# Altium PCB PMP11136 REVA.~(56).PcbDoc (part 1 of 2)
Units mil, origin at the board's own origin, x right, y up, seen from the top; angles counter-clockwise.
Board outline 4320 x 3450 mil, 4 copper layers (Top Layer, Signal Layer 1, Signal Layer 2, Bottom Layer), stack 79.834 mil thick; 234 components, 94 nets, 538 pads, 218 vias.
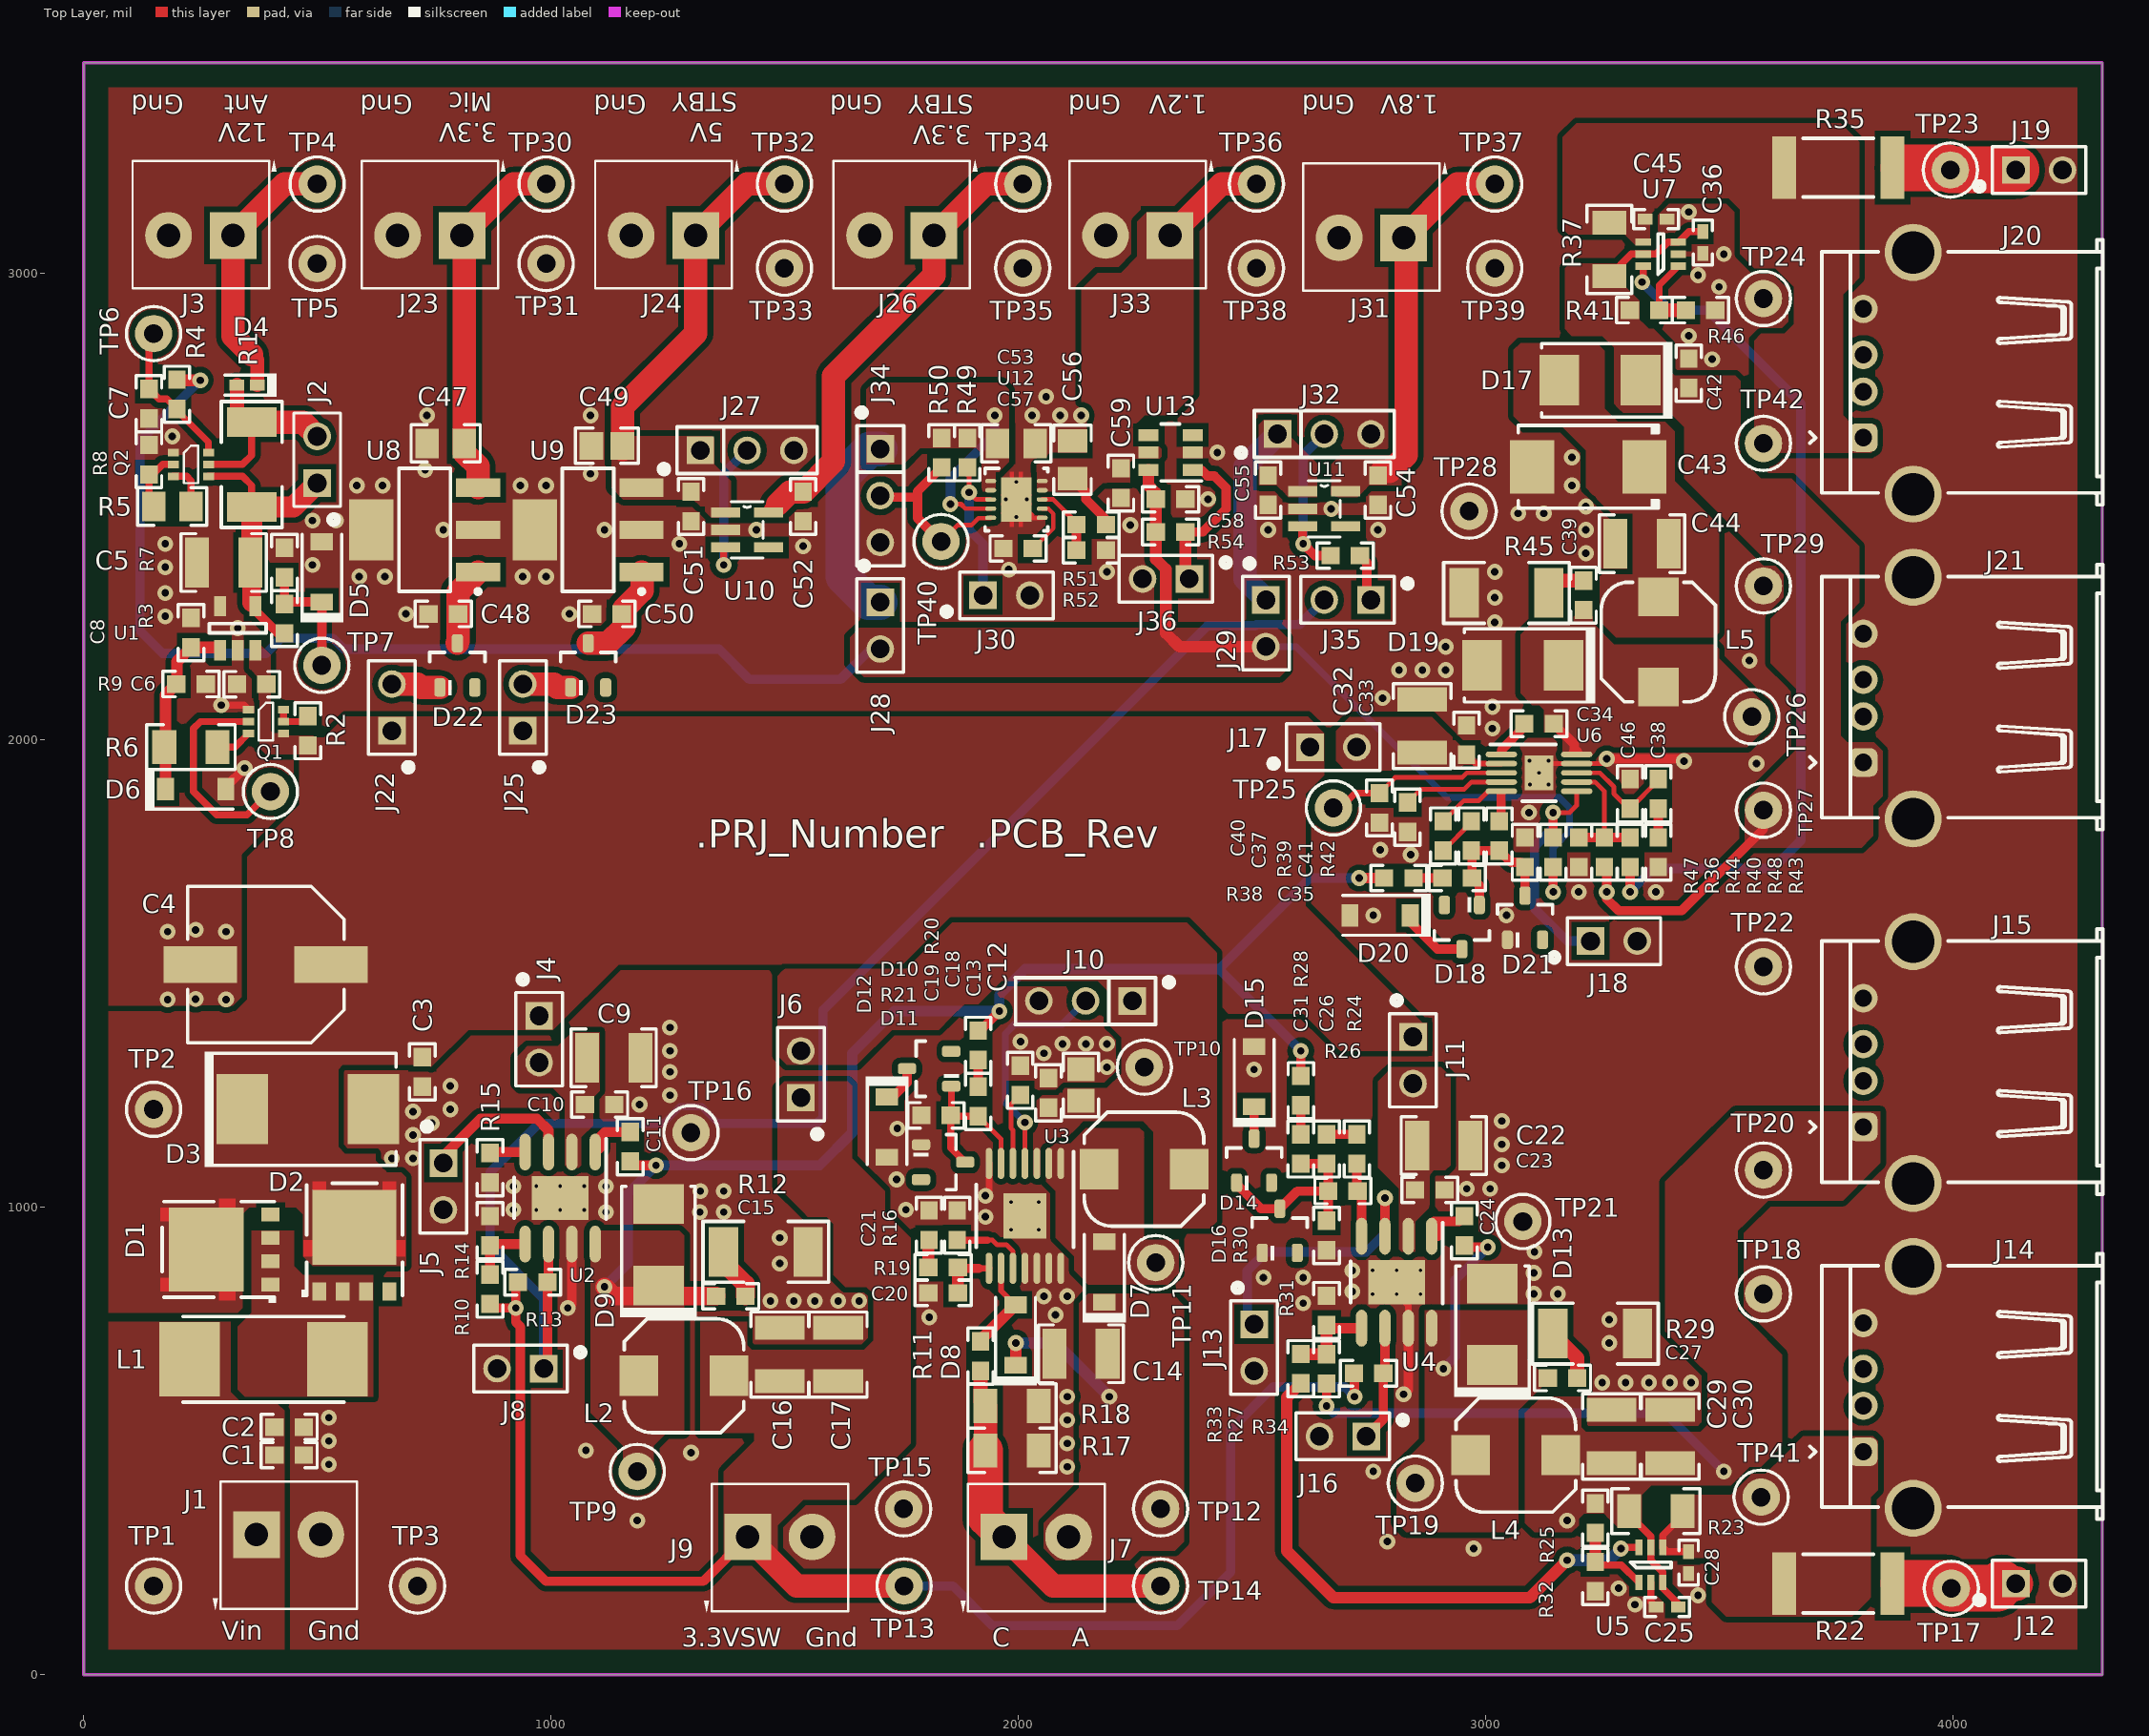
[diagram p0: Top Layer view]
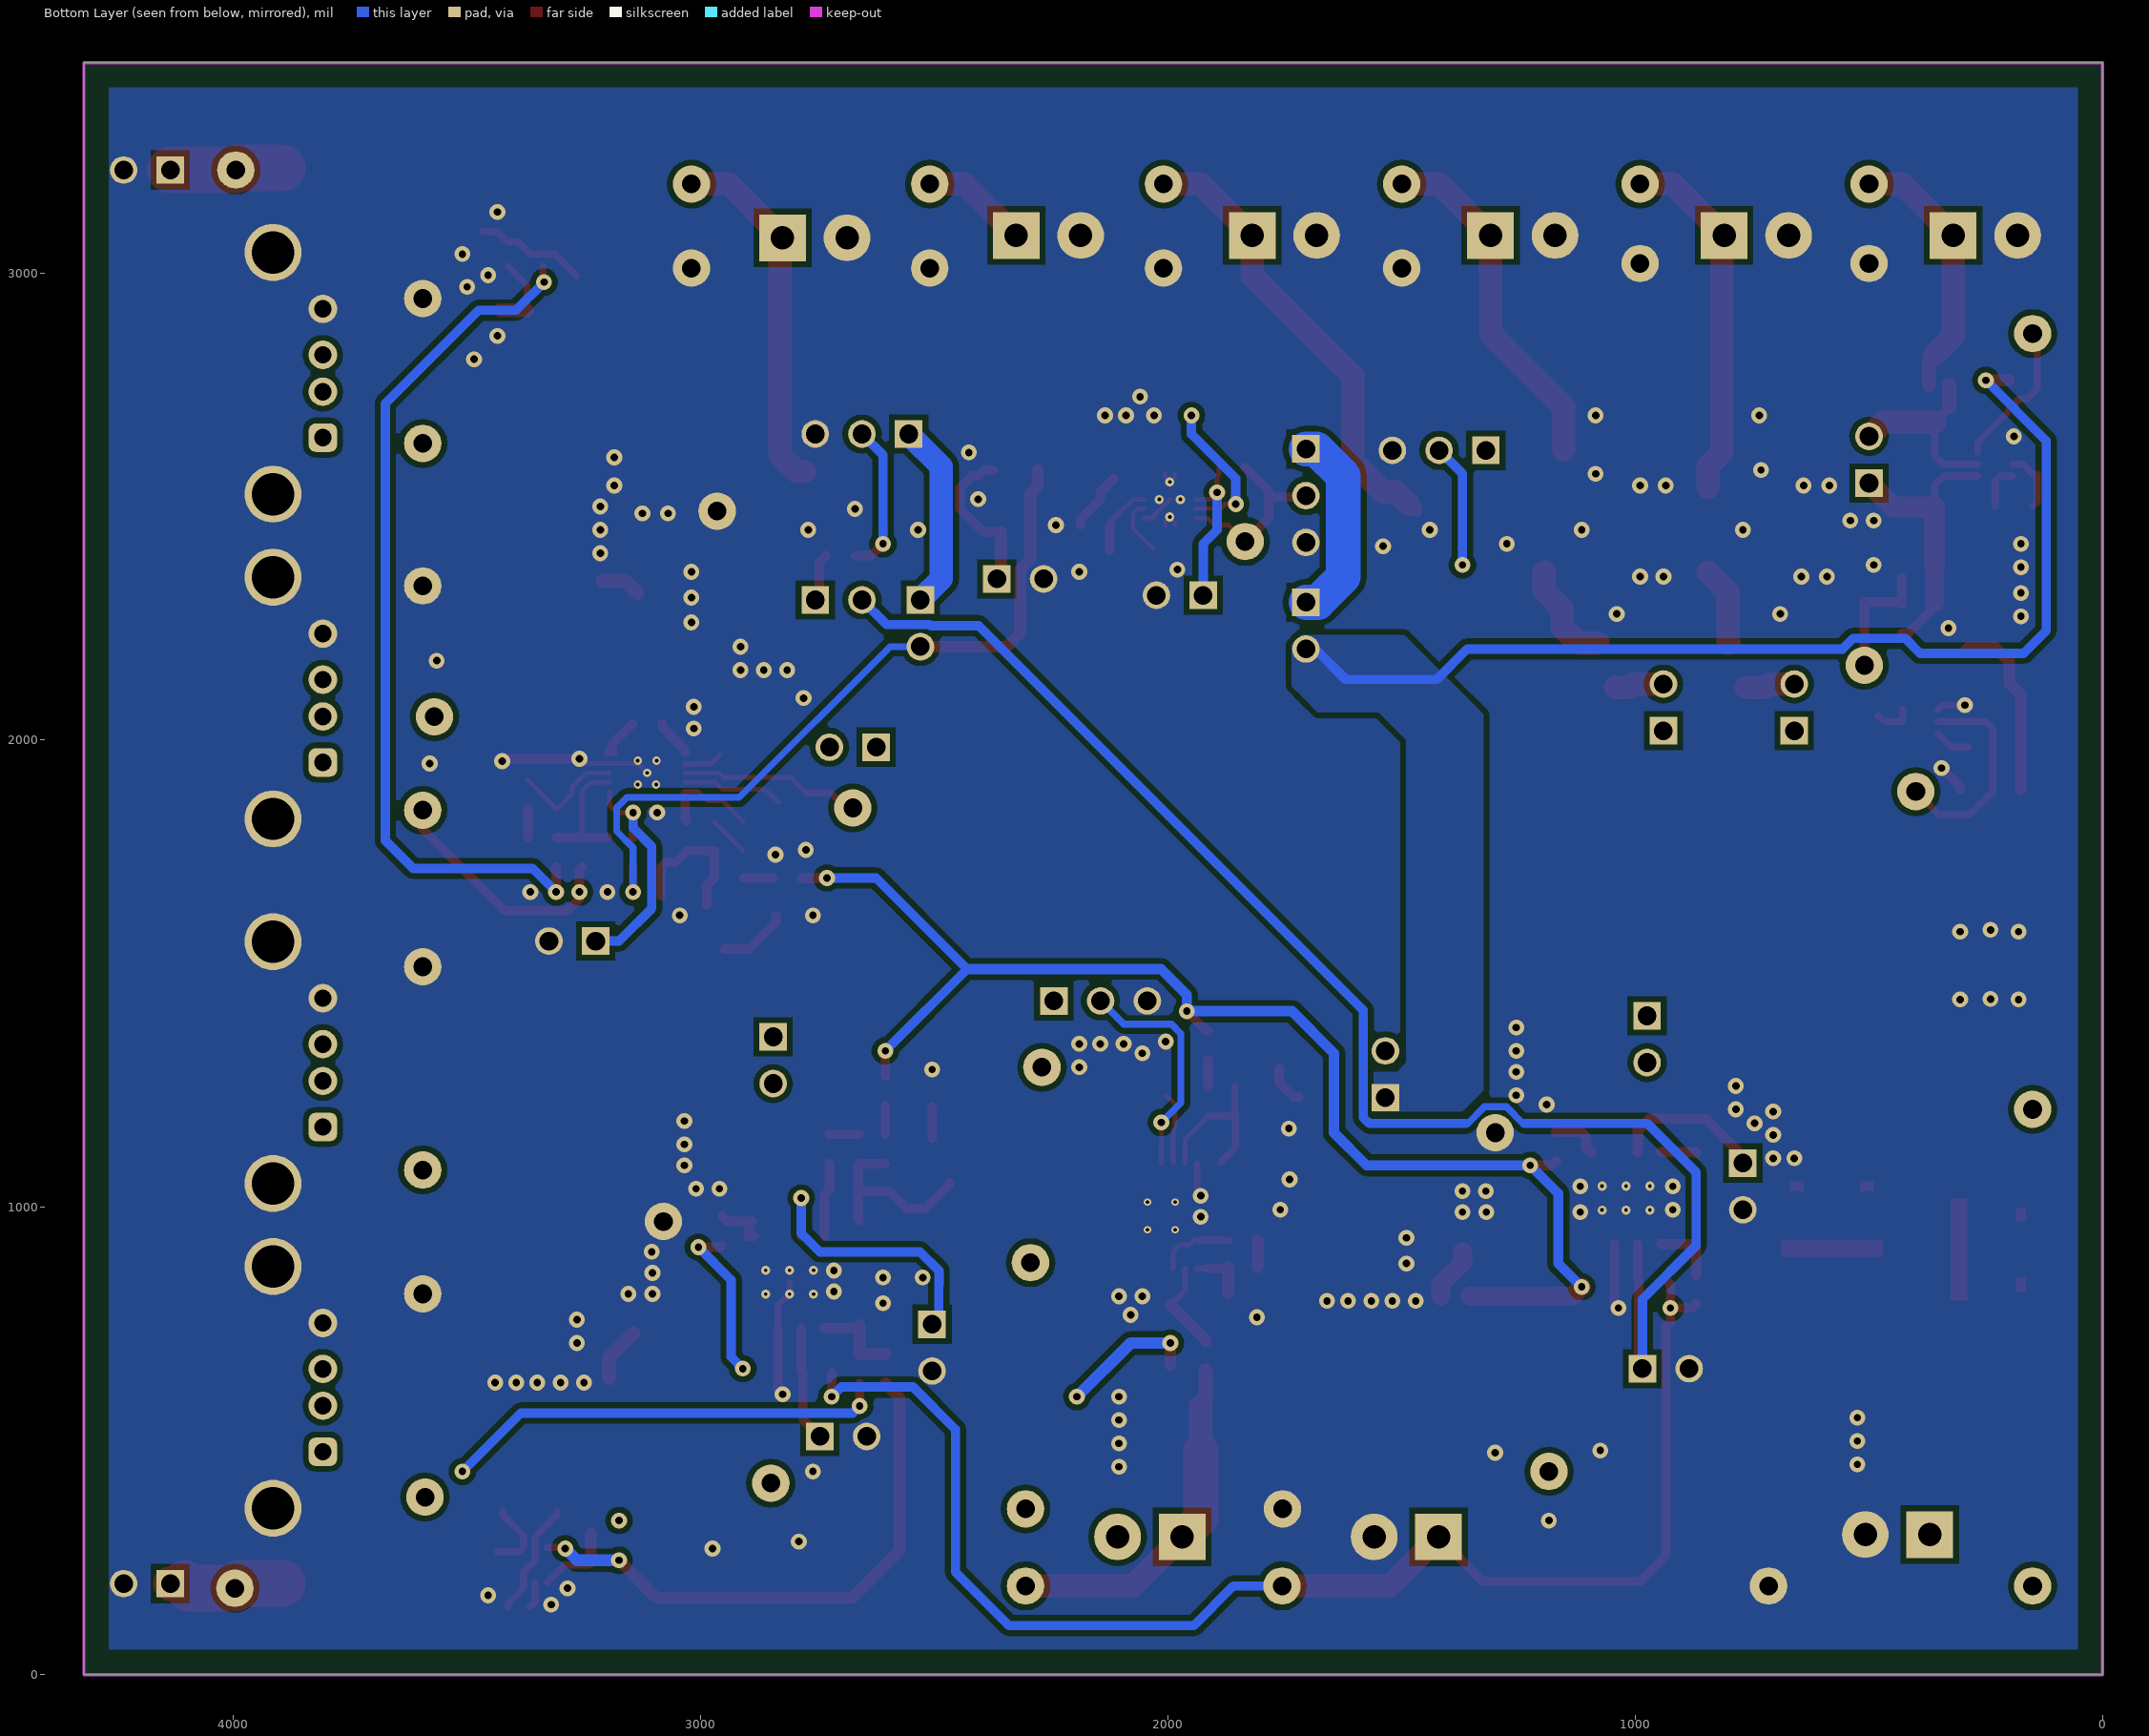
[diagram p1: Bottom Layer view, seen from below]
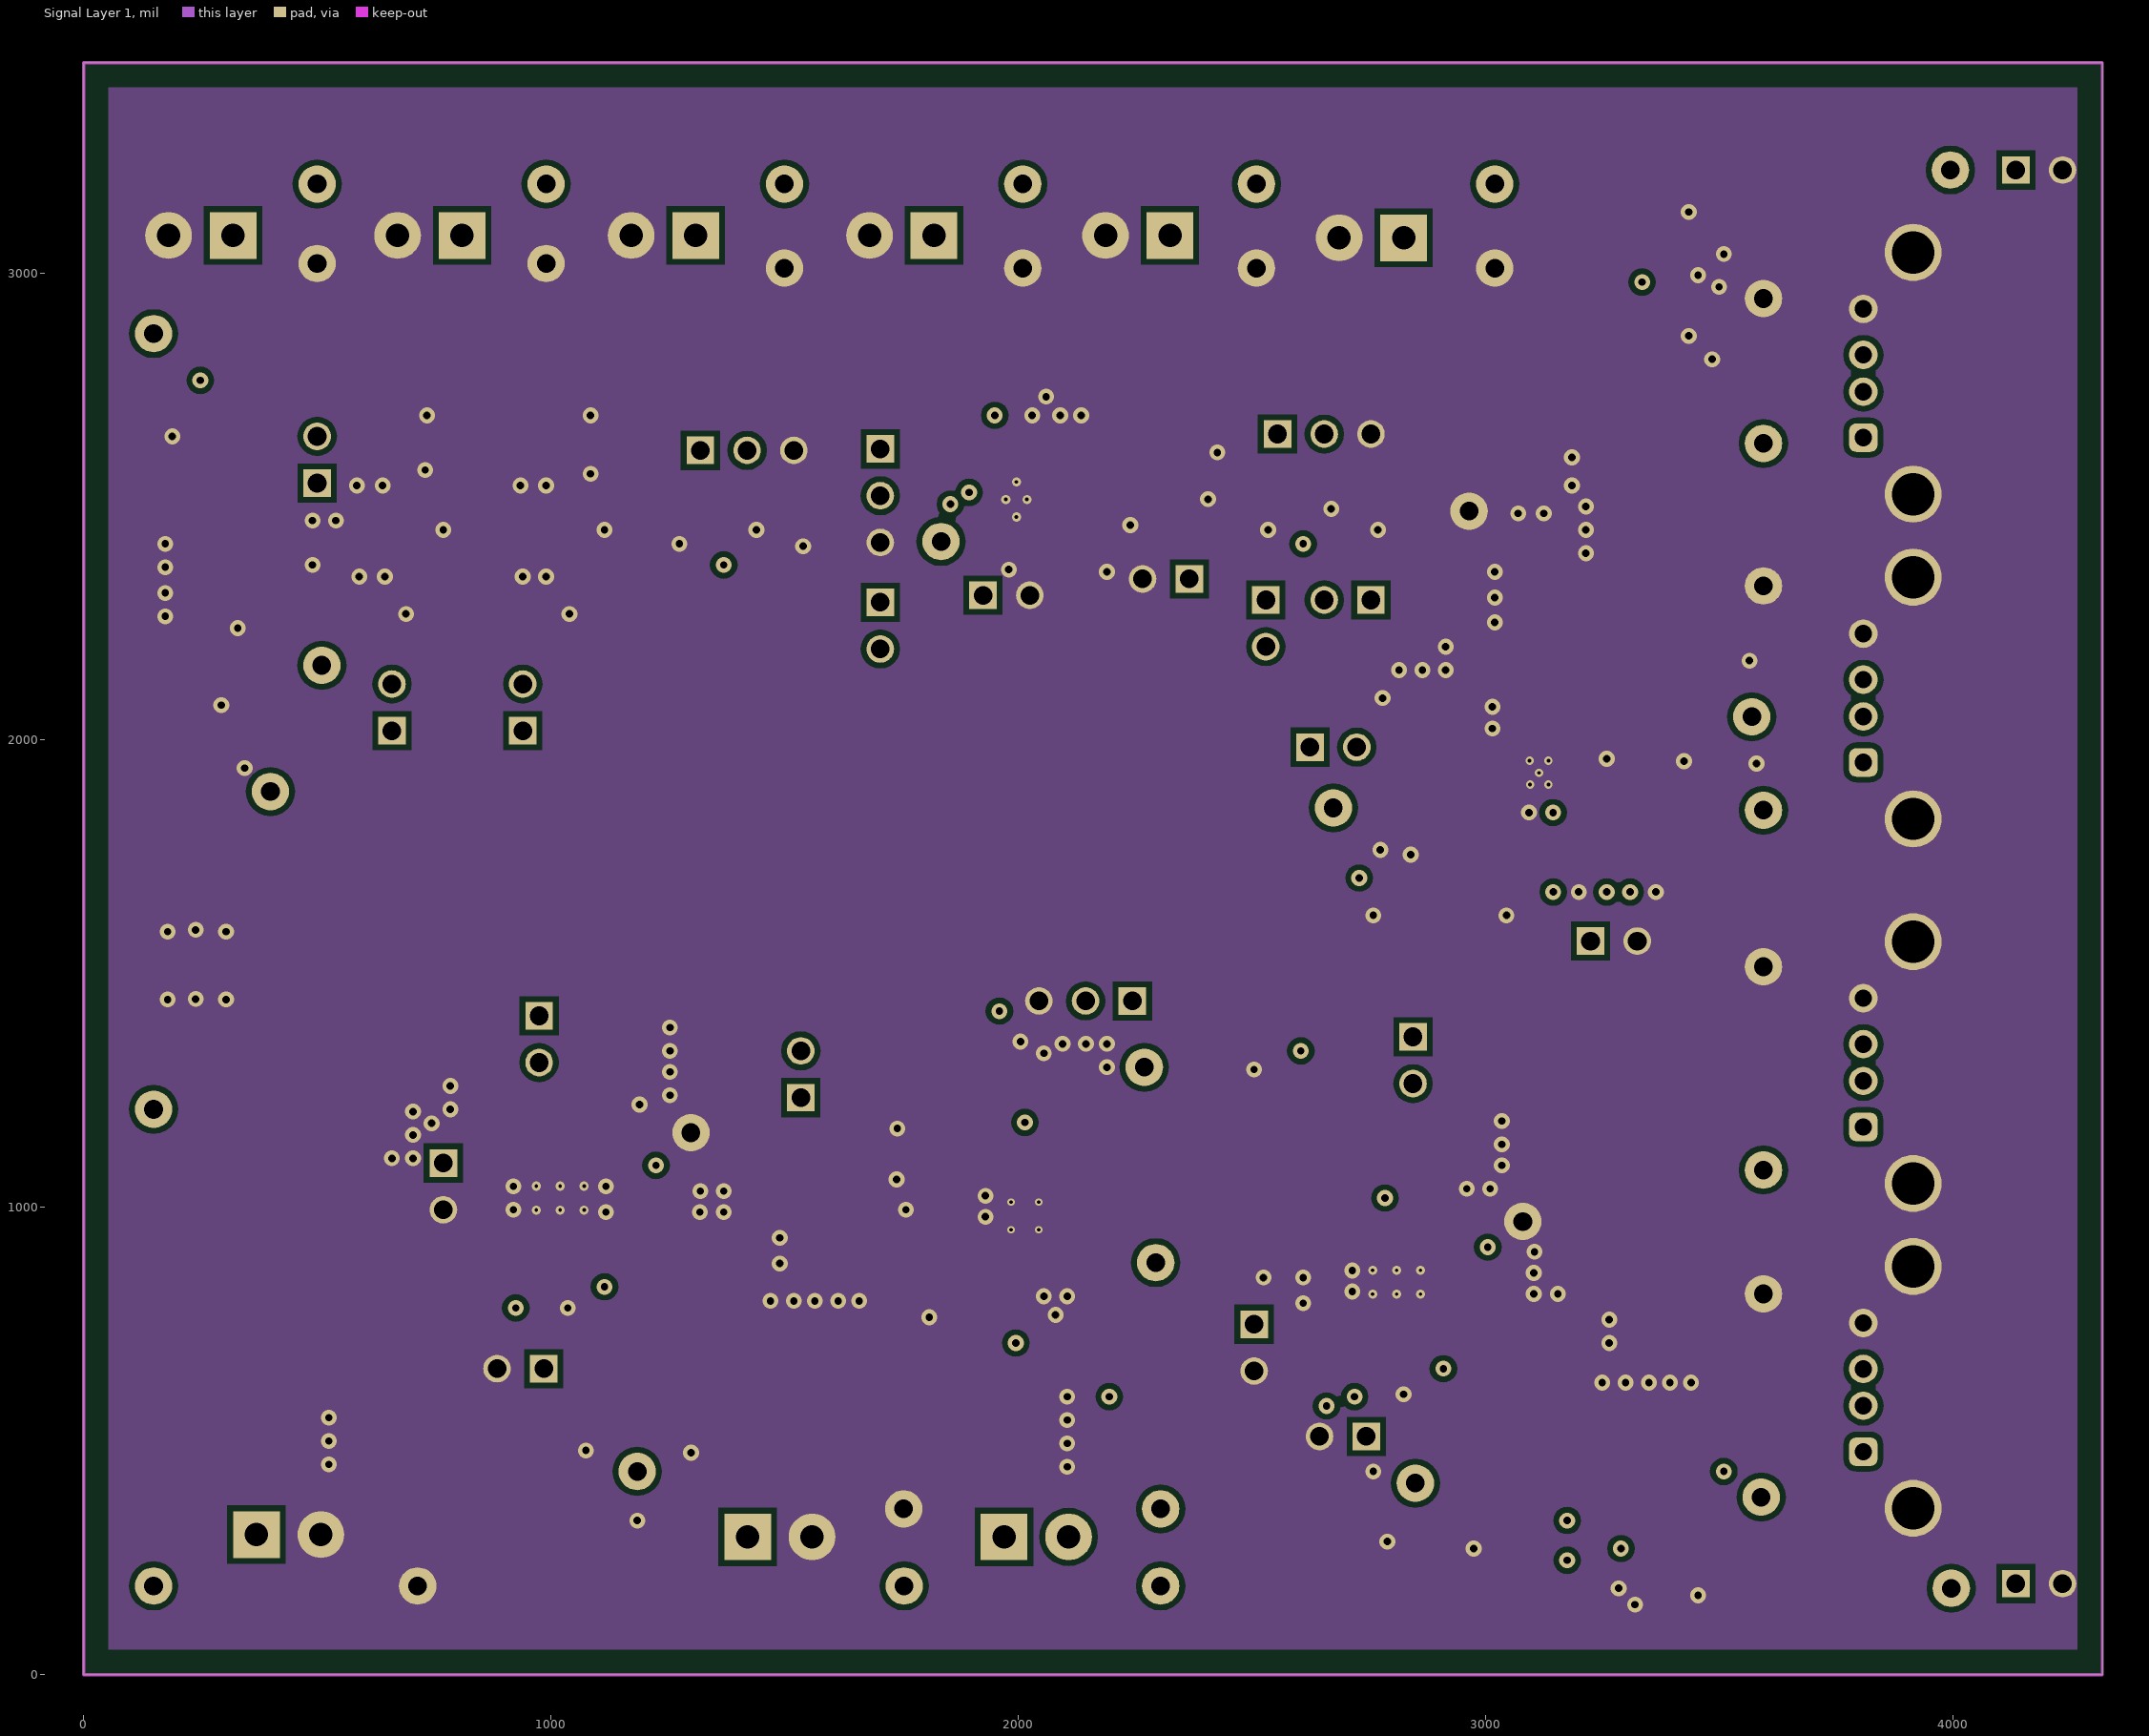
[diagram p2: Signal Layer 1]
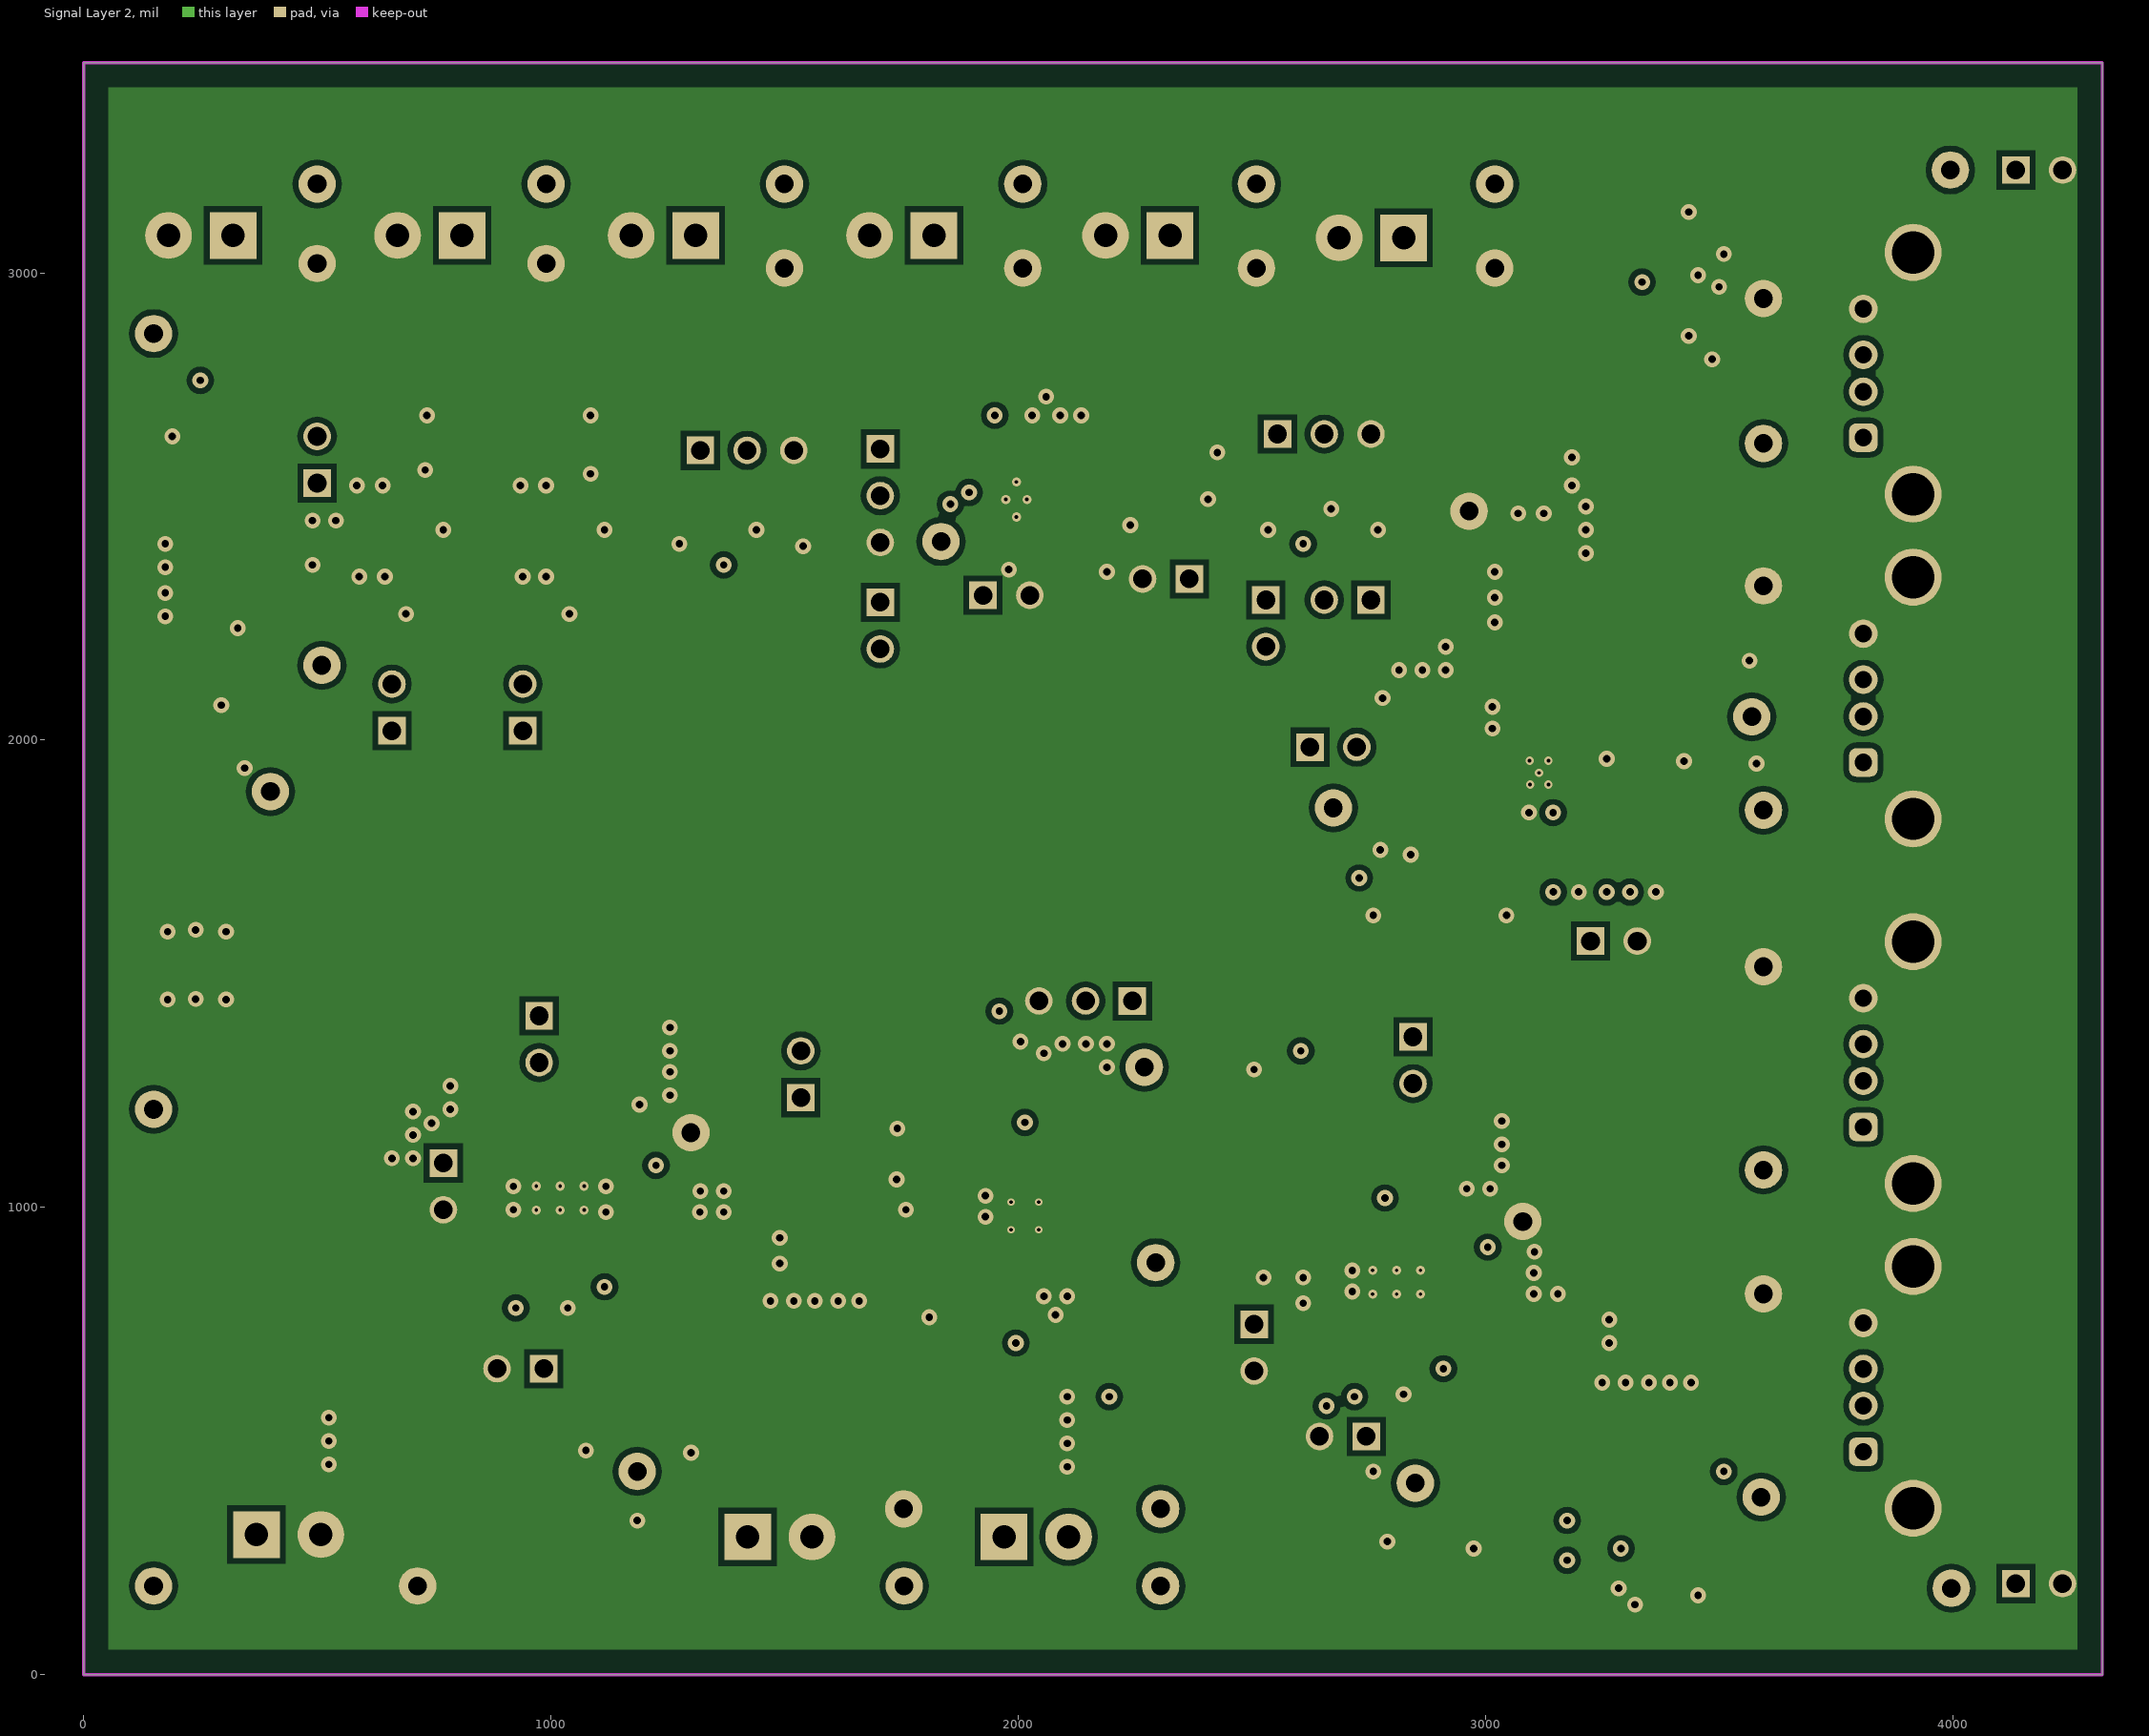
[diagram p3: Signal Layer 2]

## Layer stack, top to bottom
Top Solder: solder mask 0.4, Solder Resist, Dk 3.5
Top Layer: signal copper 1.4
Dielectric1: core 59.2, FR-4, Dk 4.8
Signal Layer 1: signal copper 1.417
Dielectric 3: prepreg 5, Dk 4.2
Signal Layer 2: signal copper 1.417
Dielectric 2: core 10, Dk 4.2
Bottom Layer: signal copper 1.4
Bottom Solder: solder mask 0.4, Solder Resist, Dk 3.5

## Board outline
0,0 4320,0 4320,3450 0,3450

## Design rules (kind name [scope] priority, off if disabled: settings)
AcuteAngle [All] p1: minimum=4.50000000000000E+0001 checktracksonly=FALSE
AssemblyTestPointUsage [All] p1: valid=2
Clearance Clearance_Keepouts [((IsTrack Or IsArc) And Not InPoly) And IsFree and IsKeepOut vs ((IsTrack Or IsArc) And Not InPoly) And IsFree and IsKeepOut] p1: gap=0
Clearance Clearance_BoardEdge_MountingHoles [OnCopper and InComponentClass('Mounting Holes') vs IsKeepOut] p2: gap=40
Clearance Clearance_BoardEdge_Poly [OnCopper and InPoly vs IsKeepOut] p3: gap=50
Clearance Clearance_BoardEdge [OnCopper and Not InComponentClass('Logo') and not InComponentClass('FiducialMark') and not InRegion(1000,500,4000,800) and Not IsKeepout vs IsKeepOut] p4: gap=50
Clearance Clearance_Poly [InPolygon] p5: gap=12
Clearance [All] p6: gap=7.87
ComponentClearance ComponentClearance_MountingHoles_FiducialMarks [InComponentClass('Mounting Holes') vs InComponentClass('FiducialMark')] p1: gap=50 collisioncheckmode=3 verticalgap=10 showdistances=FALSE
ComponentClearance ComponentClearance_Shunt [InComponentClass('Header') vs InComponentClass('Shunt')] p2: gap=0 collisioncheckmode=3 verticalgap=0 showdistances=FALSE
ComponentClearance ComponentClearance_Logo [InComponentClass('Logo')] p3: gap=50 collisioncheckmode=3 verticalgap=10 showdistances=FALSE
ComponentClearance ComponentClearance_ScrewToNut [(HasFootprint('NY PMS 440 0025 PH')) vs (HasFootprint('Keystone_1902C'))] p4: gap=5 collisioncheckmode=3 verticalgap=10 showdistances=FALSE
ComponentClearance ComponentClearance_MountingHoles [InComponentClass('Mounting Holes')] p5: gap=50 collisioncheckmode=3 verticalgap=100000 showdistances=FALSE
ComponentClearance ComponentClearance_SmallPassives [HasFootprint('0201*') or HasFootprint('0402*') or HasFootprint('0508') or HasFootprint('0603*') or HasFootprint('0612') or HasFootprint('0805*') or HasFootprint('0815*') or HasFootprint('0830*') or HasFootprint('1206*') or HasFootprint('1210*') or HasFootprint('1808*') or HasFootprint('1812*') or HasFootprint('1825*') or HasFootprint('2010*') or HasFootprint('2220*') or HasFootprint('2225*') or HasFootprint('2512*') or HasFootprint('2728*') or HasFootprint('3518*') vs HasFootprint('0201*') or HasFootprint('0402*') or HasFootprint('0508') or HasFootprint('0603*') or HasFootprint('0612') or HasFootprint('0805*') or HasFootprint('0815*') or HasFootprint('0830*') or HasFootprint('1206*') or HasFootprint('1210*') or HasFootprint('1808*') or HasFootprint('1812*') or HasFootprint('1825*') or HasFootprint('2010*') or HasFootprint('2220*') or HasFootprint('2225*') or HasFootprint('2512*') or HasFootprint('2728*') or HasFootprint('3518*')] p6: gap=10 collisioncheckmode=3 verticalgap=10 showdistances=FALSE
ComponentClearance ComponentClearance_THtoSMT [IsThruComponent vs IsSMTComponent] p7: gap=25 collisioncheckmode=3 verticalgap=30 showdistances=FALSE
ComponentClearance ComponentClearance_THtoTH [IsThruComponent vs IsThruComponent] p8: gap=25 collisioncheckmode=3 verticalgap=25 showdistances=FALSE
ComponentClearance [All] p9: gap=15 collisioncheckmode=3 verticalgap=10 showdistances=FALSE
DiffPairsRouting [All] p1: maxlimit=100 minlimit=10 mostfreqgap=10 toplayer_minwidth=15 toplayer_maxwidth=15 toplayer_prefwidth=15 midlayer1_minwidth=15 midlayer1_maxwidth=15 midlayer1_prefwidth=15 midlayer2_minwidth=15 midlayer2_maxwidth=15 midlayer2_prefwidth=15 bottomlayer_minwidth=15 bottomlayer_maxwidth=15 bottomlayer_prefwidth=15 maxuncoupledlength=1000
FabricationTestPointUsage TestPointUsage [All] p1: valid=2 allowmultiple=FALSE
FabricationTestpoint Testpoint [All] p1: side=3 testpointundercomponent=TRUE minsize=40 maxsize=100 preferedsize=60 minholesize=0 maxholesize=40 preferedholesize=32 testpointgrid=1 allowsidetop=TRUE allowsidebottom=TRUE usegrid=TRUE gridtolerance=0.01
FanoutControl Fanout_LCC [IsLCC] p1: bgadir=Out bgaviamode=Centered fanoutstyle=Auto fanoutdirection=Alternating viagrid=1 // Fanout_LCC (Default Rule)
FanoutControl Fanout_BGA [IsBGA] p2: bgadir=Out bgaviamode=Centered fanoutstyle=Auto fanoutdirection=Alternating viagrid=1 // Fanout_BGA (Default Rule)
FanoutControl Fanout_Default [All] p4: bgadir=Out bgaviamode=Centered fanoutstyle=Auto fanoutdirection=Alternating viagrid=1 // Fanout_Default (Default Rule)
FanoutControl Fanout_Small [(CompPinCount < 5)] p5: bgadir=Out bgaviamode=Centered fanoutstyle=Auto fanoutdirection=OutThenIn viagrid=1 // Fanout_Small (Default Rule)
HoleSize [All] p1: absolutevalues=TRUE maxlimit=251 minlimit=8 maxpercent=80.000 minpercent=20.000
MinimumAnnularRing MinimumAnnularRing_ThermalPadVias [IsVia and InAnyComponent] p1: minimumring=5.91
MinimumAnnularRing [All] p2: minimumring=9
MinimumSolderMaskSliver MinimumSolderMaskSliver_Logo [InComponentClass('Logo') vs InComponentClass('Logo')] p1: minsoldermaskwidth=0.7
MinimumSolderMaskSliver [All] p2: minsoldermaskwidth=3.94
PlaneClearance [All] p1: clearance=12
PlaneConnect [All] p1: planeconnectstyle=Direct reliefexpansion=10 reliefentries=4 reliefconductorwidth=10 reliefairgap=10
PolygonConnect [All] p1: connectstyle=Direct reliefconductorwidth=10 reliefentries=4 polygonreliefangle="90 Angle" airgapwidth=10
RoutingVias ThermalPadVias [IsVia and InAnyComponent] p1: holewidth=7.87 width=19.68 viastyle="Through Hole" minholewidth=7.87 minwidth=19.68 maxholewidth=12.99 maxwidth=23.62
RoutingVias [All] p2: holewidth=16 width=34 viastyle="Through Hole" minholewidth=7.87 minwidth=26 maxholewidth=40 maxwidth=65
SilkToBoardRegionClearance [Not ((IsComment or IsDesignator) And (Hide <> 'False')) and not InRegion(1000,500,4000,800)] p1:
SilkToSilkClearance SilkToSilkClearance_Pb-FreeLogo [(HasFootprint('Pb-Free_Overlay_Medium') OR HasFootprint('Pb-Free_Overlay_Small')) vs (HasFootprint('Pb-Free_Overlay_Medium') OR HasFootprint('Pb-Free_Overlay_Small'))] p1: silktosilkclearance=0
SilkToSilkClearance [All] p2: silktosilkclearance=0
SilkToSolderMaskClearance "Silk to Solder Mask Opening" [All] p1: minsilkscreentomaskgap=1 clearancetoexposedcopper=FALSE
SolderMaskExpansion [All] p1: expansion=1.97
UnpouredPolygon [All] p1: allowunpoured=FALSE
Width [All] p1: maxlimit=100 minlimit=6 preferedwidth=10 checkconnectedcopper=TRUE
13 further rules are at their usual default settings.

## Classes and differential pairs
component class Header: J2 J4 J5 J6 J8 J10 J11 J12 J13 J16 J17 J18 J19 J22 J25 J27 J28 J29 J30 J32 J34 J35 J36
component class "PMP11136 REVA SHEET1": C1 C2 C3 C4 C5 C6 C7 C8 C9 C10 C11 C12 C13 C14 C15 C16 C17 C18 C19 C20 C21 D1 D2 D3 D4 D5 D6 D7 D8 D9 D10 D11 D12 J1 J2 J3 J4 J5 J6 J7 J8 J9 J10 L1 L2 L3 Q1 Q2 R1 R2 R3 R4 R5 R6 R7 R8 R9 R10 R11 R12 R13 R14 R15 R16 R17 R18 R19 R20 R21 TP1 TP2 TP3 TP4 TP5 TP6 TP7 TP8 TP9 TP10 TP11 TP12 TP13 TP14 TP15 TP16 U1 U2 U3
component class "PMP11136 REVA SHEET2": C22 C23 C24 C25 C26 C27 C28 C29 C30 C31 C32 C33 C34 C35 C36 C37 C38 C39 C40 C41 C42 C43 C44 C45 C46 D13 D14 D15 D16 D17 D18 D19 D20 D21 J11 J12 J13 J14 J15 J16 J17 J18 J19 J20 J21 L4 L5 R22 R23 R24 R25 R26 R27 R28 R29 R30 R31 R32 R33 R34 R35 R36 R37 R38 R39 R40 R41 R42 R43 R44 R45 R46 R47 R48 TP17 TP18 TP19 TP20 TP21 TP22 TP23 TP24 TP25 TP26 TP27 TP28 TP29 TP41 TP42 U4 U5 U6 U7
component class "PMP11136 REVA SHEET3": C47 C48 C49 C50 C51 C52 C53 C54 C55 C56 C57 C58 C59 D22 D23 J22 J23 J24 J25 J26 J27 J28 J29 J30 J31 J32 J33 J34 J35 J36 R49 R50 R51 R52 R53 R54 TP30 TP31 TP32 TP33 TP34 TP35 TP36 TP37 TP38 TP39 TP40 U8 U9 U10 U11 U12 U13

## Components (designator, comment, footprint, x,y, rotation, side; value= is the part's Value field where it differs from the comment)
C1 "C1608C0G2A102J" 0603 440,470 r0 top
C2 "C1608X7R2A103K" 0603 440,530 r0 top
C3 "C1608X7R1H224K080AB" 0603 725,1290 r270 top
C4 "EEE-FK1H101P" SM_RADIAL_F 390,1520 r180 top
C5 "C3225X7R1H475M250AB" 1210 300,2380 r0 top
C6 "C1608X7R1E105K" 0603 360,2119.68 r180 top
C7 "C1608X7R1H104K" 0603 140,2720 r270 top
C8 "C1608X7R1H103K" 0603 230,2230 r90 top
C9 "C3225X7R1H475M250AB" 1210 1134.43,1320 r180 top
C10 "C1608X7R1H104K" 0603 1104.43,1220 r0 top
C11 "C1608X7R1H104K" 0603 1170,1130 r270 top
C12 "GRM21BR71A106KE51L" 0805 2134.49,1261.91 r90 top
C13 "C1608X7R1E105K" 0603 2065,1245 r90 top
C14 "C3225X7R1C226M250AC" 1210 2134.49,686.91 r180 top
C15 "" 0603 1385,810 r0 top
C16 "C3225X7R1C226M250AC" 1210 1490,685 r90 top
C17 "" 1210 1615,685 r90 top
C18 "C1608X7R1H473K" 0603 2004.49,1271.91 r90 top
C19 "C1608C0G1H151J" 0603 1914.49,1226.91 r90 top
C20 "" 0603 1839.49,816.91 r180 top
C21 "C1608C0G1E682J" 0603 1809.49,961.91 r90 top
C22 "C3225X7R1H475M250AB" 1210 2911,1132.52 r180 top
C23 "C1608X7R1H104K" 0603 2881,1037.52 r0 top
C24 "C1608X7R1H104K" 0603 2955,950 r270 top
C25 "C1005X7R1H104K050BB" 0402 3389.01,145 r180 top
C26 "C1608C0G1H100D" 0603 2660,1125 r270 top
C27 "" 0603 3165,635 r0 top
C28 "C1005X7R1H104K050BB" 0402 3435,240 r270 top
C29 "C3225X7R1C226M250AC" 1210 3270,510 r90 top
C30 "" 1210 3395,510 r90 top
C31 "C1608C0G1H151J" 0603 2605,1125 r90 top
C32 "C3225X7R1H475M250AB" 1210 2864.68,2030 r270 top
C33 "C1608X7R1H104K" 0603 2959.68,2000 r90 top
C34 "C1608X7R1H104K" 0603 3114.68,2035 r0 top
C35 "C1608C0G1H151J" 0603 2939.68,1705 r180 top
C36 "C1005X7R1H104K050BB" 0402 3465.31,3065 r270 top
C37 "C1608X7R1H223K" 0603 2833.23,1835 r270 top
C38 "C1608C0G1H152J" 0603 3369.68,1885 r270 top
C39 "" 0603 3210,2310 r90 top
C40 "" 0603 2773.23,1855 r270 top
C41 "C1608C0G1H100D" 0603 2969.68,1795 r270 top
C42 "C1608X7R1H104K" 0603 3435,2785 r90 top
C43 "" 7343-40 3220,2585 r180 top
C44 "C3225X7R1C226M250AC" 1210 3335,2420 r180 top
C45 "C1005X7R1H104K050BB" 0402 3365.31,3115 r0 top
C46 "C1608C0G1H100D" 0603 3309.68,1885 r90 top
C47 "GRM21BR71A106KE51L" 0805_HV 775,2635 r180 top
C48 "C1608X7R1H104K" 0603 770,2270 r180 top
C49 "GRM21BR71A106KE51L" 0805 1120,2630 r180 top
C50 "C1608X7R1H104K" 0603 1120,2270 r180 top
C51 "C1608X7R1E105K" 0603 1300,2500 r270 top
C52 "C1608X7R1E105K" 0603 1540,2500 r270 top
C53 "GRM21BR71A106KE51L" 0805_HV 1996.3,2635 r0 top
C54 "C1608X7R1E105K" 0603 2770,2535 r270 top
C55 "C1608X7R1E105K" 0603 2535,2535 r270 top
C56 "GRM21BR71A106KE51L" 0805_HV 2116.3,2600 r90 top
C57 "" 0603 2000,2410 r180 top
C58 "C1608X7R1H104K" 0603 2326.3,2515.47 r0 top
C59 "C1608C0G2A102J" 0603 2220,2550 r270 top
D1 "MBR1045MFST1G" SO-8FL 290,910 r180 top
D2 "MBR1045MFST1G" SO-8FL 580,930 r90 top
D3 "1.5SMC33AT3G" SMC 480,1210 r0 top
D4 "1PS79SB30" SOD-523 350,2760 r180 top
D5 "MMSZ4684T1G" SOD-123 510,2360 r90 top
D6 "MMSZ4705T1G" SOD-123 240,1895 r0 top
D7 "RB070M-30" SOD-123 2184.49,861.91 r90 top
D8 "MMSZ4699T1G" SOD-123 1994.49,726.91 r90 top
D9 "MBRS360BT3G" SMB 1230.31,920 r90 top
D10 "BAS16-7-F" SOT-23 1809.49,1296.91 r180 top
D11 "BAS16-7-F" SOT-23 1839.49,1096.91 r0 top
D12 "MMSZ5221B-7-F" SOD-123 1719.49,1171.91 r270 top
D13 "MBRS360BT3G" SMB 3015,750 r90 top
D14 "BAS16-7-F" SOT-23 2505,1100 r90 top
D15 "MMSZ5221B-7-F" SOD-123 2505,1280 r90 top
D16 "BAS16-7-F" SOT-23 2560,950 r90 top
D17 "MBRS260T3G" SMB 3245,2770 r180 top
D18 "BAS16-7-F" SOT-23 2949.68,1600 r270 top
D19 "MBRS260T3G" SMB 3080,2160 r180 top
D20 "MMSZ5221B-7-F" SOD-123 2774.68,1625 r180 top
D21 "BAS16-7-F" SOT-23 3084.68,1620 r90 top
D22 "BAS16-7-F" SOT-23 800,2160 r90 top
D23 "BAS16-7-F" SOT-23 1080,2160 r90 top
J1 "ED555/2DS" TERM_BLK_ED555-2DS 370,300 r0 top
J2 "PEC02SAAN" CONN_PEC02SAAN 500,2600 r90 top
J3 "ED555/2DS" TERM_BLK_ED555-2DS 320,3080 r180 top
J4 "PEC02SAAN" CONN_PEC02SAAN 975,1360 r270 top
J5 "PEC02SAAN" CONN_PEC02SAAN 770,1045 r270 top
J6 "PEC02SAAN" CONN_PEC02SAAN 1535,1285 r90 top
J7 "ED555/2DS" TERM_BLK_ED555-2DS 1970,295 r0 top
J8 "PEC02SAAN" CONN_PEC02SAAN 935,655 r180 top
J9 "ED555/2DS" TERM_BLK_ED555-2DS 1421.1,295 r0 top
J10 "PEC03SAAN" CONN_PEC03SAAN 2144.49,1441.91 r180 top
J11 "PEC02SAAN" CONN_PEC02SAAN 2845,1315 r270 top
J12 "PEC02SAAN" CONN_PEC02SAAN 4185,195 r0 top
J13 "PEC02SAAN" CONN_PEC02SAAN 2505,700 r270 top
J14 "676430910" MOLEX_0676430910 3915,615 r90 top
J15 "676430910" MOLEX_0676430910 3915,1310 r90 top
J16 "PEC02SAAN" CONN_PEC02SAAN 2695,510 r180 top
J17 "PEC02SAAN" CONN_PEC02SAAN 2674.68,1985 r0 top
J18 "PEC02SAAN" CONN_PEC02SAAN 3275,1570 r0 top
J19 "PEC02SAAN" CONN_PEC02SAAN 4185,3220 r0 top
J20 "676430910" MOLEX_0676430910 3915,2785 r90 top
J21 "676430910" MOLEX_0676430910 3915,2090 r90 top
J22 "PEC02SAAN" CONN_PEC02SAAN 660,2070 r90 top
J23 "ED555/2DS" TERM_BLK_ED555-2DS 810,3080 r180 top
J24 "ED555/2DS" TERM_BLK_ED555-2DS 1310,3080 r180 top
J25 "PEC02SAAN" CONN_PEC02SAAN 940,2070 r90 top
J26 "ED555/2DS" TERM_BLK_ED555-2DS 1820,3080 r180 top
J27 "PEC03SAAN" CONN_PEC03SAAN 1420,2620 r0 top
J28 "PEC02SAAN" CONN_PEC02SAAN 1705,2245 r270 top
J29 "PEC02SAAN" CONN_PEC02SAAN 2530,2250 r270 top
J30 "PEC02SAAN" CONN_PEC02SAAN 1975,2310 r0 top
J31 "ED555/2DS" TERM_BLK_ED555-2DS 2825,3075 r180 top
J32 "PEC03SAAN" CONN_PEC03SAAN 2655,2655 r0 top
J33 "ED555/2DS" TERM_BLK_ED555-2DS 2325,3080 r180 top
J34 "PEC03SAAN" CONN_PEC03SAAN 1705,2523.02 r270 top
J35 "PEC02SAAN" CONN_PEC02SAAN 2705,2300 r180 top
J36 "PEC02SAAN" CONN_PEC02SAAN 2316.3,2345 r180 top
L1 "28F0181-1SR-10" 28F0181 385,675 r0 top
L2 "CLF6045NIT-2R2N-D" CLF6045NI-D 1285,640 r0 top
L3 "CLF6045NIT-4R7N-D" CLF6045NI-D 2269.49,1081.91 r180 top
L4 "CLF6045NIT-2R2N-D" CLF6045NI-D 3065,470 r0 top
L5 "CLF6045NIT-4R7N-D" CLF6045NI-D 3370,2210 r90 top
Q1 "BCR22PN" SOT-363 390.35,2039.77 r0 top
Q2 "BC847PN" SOT-363 230,2590 r0 top
R1 "CRCW20107R50JNEF" 2010 360,2589.69 r90 top
R2 "CRCW060320K0FKEA" 0603 480,2020 r270 top
R3 "CRCW060310K0FKEA" 0603 430,2260 r270 top
R4 "CRCW060310K0FKEA" 0603 200,2740 r90 top
R5 "CRCW080510K0FKEA" 0805_HV 190,2500 r0 top
R6 "CRCW12062K00FKEA" 1206 230,1985 r180 top
R7 "CRCW06032K87FKEA" 0603 430,2380 r90 top
R8 "CRCW06033K01FKEA" 0603 140,2600 r270 top
R9 "CRCW0603100KFKEA" 0603 230,2120 r0 top
R10 "CRCW060334K0FKEA" 0603 870,825 r270 top
R11 "CRCW0603110RFKEA" 0603 1919.49,681.91 r90 top
R12 "" 2010 1460,905 r180 top
R13 "CRCW060310K0FKEA" 0603 961.3,840 r0 top
R14 "CRCW060310K0FKEA" 0603 870,950 r270 top
R15 "" 0603 870,1085 r90 top
R16 "CRCW060353K6FKEA" 0603 1869.49,961.91 r270 top
R17 "CRCW120615R0FKEA" 1206 1987.09,480 r180 top
R18 "CRCW120615R0FKEA" 1206 1987.09,575 r180 top
R19 "CRCW060310K0FKEA" 0603 1839.49,871.91 r0 top
R20 "CRCW06030000Z0EA" 0603 1914.49,1346.91 r270 top
R21 "CRCW0603200RFKEA" 0603 1824.49,1196.91 r0 top
R22 "CSRN2512FKR200" 2512 3755,195 r0 top
R23 "CSR1206FK10L0" 1206 3365,350 r0 top
R24 "CRCW06034K02FKEA" 0603 2725,1125 r90 top
R25 "CRCW06034K99FKEA" 0603 3235,335 r270 top
R26 "" 0603 2695,1035 r0 top
R27 "CRCW060363K4FKEA" 0603 2660,654.45 r270 top
R28 "CRCW06030000Z0EA" 0603 2605,1250 r270 top
R29 "" 2010 3235,730 r180 top
R30 "CRCW0603200RFKEA" 0603 2660,940 r90 top
R31 "CRCW060310K0FKEA" 0603 2660,779.45 r270 top
R32 "CRCW06034K99FKEA" 0603 3235,210 r270 top
R33 "CRCW0603124KFKEA" 0603 2605,655 r90 top
R34 "CRCW060310K0FKEA" 0603 2750,645 r0 top
R35 "CSRN2512FKR200" 2512 3755,3225 r0 top
R36 "CRCW060310K0FKEA" 0603 3144.68,1760 r90 top
R37 "CSR1206FK10L0" 1206 3265.31,3050 r90 top
R38 "CRCW06030000Z0EA" 0603 2814.68,1705 r0 top
R39 "CRCW06034K02FKEA" 0603 2909.68,1795 r270 top
R40 "CRCW060363K4FKEA" 0603 3254.68,1760 r270 top
R41 "CRCW06034K99FKEA" 0603 3340.33,2920 r0 top
R42 "CRCW060354K9FKEA" 0603 3029.68,1795 r90 top
R43 "CRCW0603100KFKEA" 0603 3369.68,1760 r90 top
R44 "CRCW060310K0FKEA" 0603 3199.68,1760 r90 top
R45 "" 2010 3045,2315 r0 top
R46 "CRCW06034K99FKEA" 0603 3460.33,2920 r0 top
R47 "CRCW0603200RFKEA" 0603 3084.68,1760 r270 top
R48 "CRCW0603124KFKEA" 0603 3309.68,1760 r90 top
R49 "CRCW060310K0FKEA" 0603 1891.3,2615 r90 top
R50 "CRCW060310K0FKEA" 0603 1836.3,2615 r90 top
R51 "CRCW06032K49FKEA" 0603 2156.3,2461.3 r0 top
R52 "CRCW06034K99FKEA" 0603 2156.3,2406.3 r180 top
R53 "CRCW060310K0FKEA" 0603 2700,2395 r180 top
R54 "CRCW060349K9FKEA" 0603 2326.3,2445.47 r180 top
TP1 "5000" Keystone5000 150,190 r0 top
TP2 "5000" Keystone5000 150,1210 r0 top
TP3 "5001" Keystone5001 715,190 r0 top
TP4 "5000" Keystone5000 500,3190 r0 top
TP5 "5001" Keystone5001 500,3020 r0 top
TP6 "5000" Keystone5000 150,2870 r0 top
TP7 "5000" Keystone5000 510,2160 r0 top
TP8 "5000" Keystone5000 400,1890 r0 top
TP9 "5000" Keystone5000 1185,435 r270 top
TP10 "5000" Keystone5000 2270,1300 r0 top
TP11 "5000" Keystone5000 2294.49,881.91 r270 top
TP12 "5000" Keystone5000 2305,355 r0 top
TP13 "5000" Keystone5000 1756.1,190 r0 top
TP14 "5001" Keystone5001 2305,190 r0 top
TP15 "5001" Keystone5001 1755,355 r0 top
TP16 "5001" Keystone5001 1300,1160 r0 top
TP17 "5000" Keystone5000 3996.97,185 r0 top
TP18 "5001" Keystone5001 3595,815 r0 top
TP19 "5000" Keystone5000 2850,410 r270 top
TP20 "5000" Keystone5000 3595,1080 r0 top
TP21 "5001" Keystone5001 3080,970 r0 top
TP22 "5001" Keystone5001 3595,1515 r0 top
TP23 "5000" Keystone5000 3995,3220 r0 top
TP24 "5001" Keystone5001 3595,2945 r0 top
TP25 "5000" Keystone5000 2674.68,1855 r0 top
TP26 "5000" Keystone5000 3570,2050 r0 top
TP27 "5000" Keystone5000 3595,1850 r0 top
TP28 "5001" Keystone5001 2965,2490 r0 top
TP29 "5001" Keystone5001 3595,2330 r0 top
TP30 "5000" Keystone5000 990,3190 r0 top
TP31 "5001" Keystone5001 990,3020 r0 top
TP32 "5000" Keystone5000 1500,3190 r0 top
TP33 "5001" Keystone5001 1500,3010 r0 top
TP34 "5000" Keystone5000 2010,3190 r0 top
TP35 "5001" Keystone5001 2010,3010 r0 top
TP36 "5000" Keystone5000 2510,3190 r0 top
TP37 "5000" Keystone5000 3020,3190 r0 top
TP38 "5001" Keystone5001 2510,3010 r0 top
TP39 "5001" Keystone5001 3020,3010 r0 top
TP40 "5000" Keystone5000 1835,2425 r180 top
TP41 "5000" Keystone5000 3590,380 r0 top
TP42 "5000" Keystone5000 3595,2635 r0 top
U1 "TPS7B4250QDBV" DBV0005A_N 330,2239.68 r90 top
U2 "LMR14030PQDDAQ1" DDA0008E_N 1020,1020 r270 top
U3 "TPS61175PWP" PWP0014E_N 2014.49,981.91 r270 top
U4 "LMR14030PQDDAQ1" DDA0008E_N 2810,840 r270 top
U5 "INA213AQDCKRQ1" DCK0006A_N 3354.01,235 r90 top
U6 "TPS57140QDGQRQ1" DGQ0010D_NV_N 3114.68,1930 r0 top
U7 "INA213AQDCKRQ1" DCK0006A_N 3375.31,3040 r180 top
U8 "TPS7B6933QDCYRQ1" DCY0004A_N 730,2450 r180 top
U9 "TPS7B6950QDCYRQ1" DCY0004A_N 1080,2450 r180 top
U10 "TLV70033QDDCRQ1" DDC0005A_N 1420,2450 r0 top
U11 "TLV70018QDDCRQ1" DDC0005A_N 2655,2495 r0 top
U12 "TPS74701QDRCRQ1" DRC0010A 1996.3,2515 r0 top
U13 "TPS3808G12QDBVRQ1" DBV0006A_N 2326.3,2615.47 r180 top

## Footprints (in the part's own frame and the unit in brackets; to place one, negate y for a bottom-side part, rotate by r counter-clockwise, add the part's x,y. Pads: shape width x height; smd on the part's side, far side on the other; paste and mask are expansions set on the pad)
28F0181 [mm] "SMD, 2-Leads, Body 8.74x4.65mm"
  rect 3.3x4.06 smd: 1(-4.015,0) 2(4.015,0)
  silkscreen extent -4.37,-2.32 4.37,2.32, body extent -4.76,-2.32 4.77,2.32, height 3.05
0402 [mm] "0402 from SM-752 data"
  rect 0.8x0.6 smd: 1(-0.6,0) 2(0.6,0)
  silkscreen extent -1.22,-0.52 1.22,0.52, body extent -0.55,-0.3 0.55,0.3, height 0.6
0603 [mm] "0603 from SM-752 data"
  rect 1x0.95 smd: 1(-0.8,0) 2(0.8,0)
  silkscreen extent -1.52,-0.69 1.52,0.69, body extent -0.87,-0.47 0.87,0.47, height 0.85
0805 [mm] "0805 from SM-752 data"
  rect 1.3x1.5 smd: 1(-0.85,0) 2(0.85,0)
  silkscreen extent -1.72,-0.97 1.72,0.97, body extent -1.1,-0.72 1.1,0.72, height 1.1
0805_HV [mil] "0805 with 30mil clearance between pads"
  rect 50x63 smd: 1(-40,0) 2(40,0)
  silkscreen extent -74,-40 74,40, body extent -43,-29 43,29, height 43
1206 [mm] "1206 from SM-752 data"
  rect 1.3x1.85 smd: 1(-1.45,0) 2(1.45,0)
  silkscreen extent -2.4,-1.21 2.4,1.21, body extent -1.7,-0.9 1.7,0.9, height 1.35
1210 [mm] "1210 from SM-752 data"
  rect 1.3x2.7 smd: 1(-1.45,0) 2(1.45,0)
  silkscreen extent -2.32,-1.57 2.32,1.57, body extent -1.7,-1.35 1.7,1.35, height 1.35
2010 [mm] "Chip Capacitor, Body 5.08x2.54mm, IPC Medium Density"
  rect 1.6x2.7 smd: 1(-2.3,0) 2(2.3,0)
  silkscreen extent -3.42,-1.65 3.42,1.65, body extent -2.73,-1.45 2.73,1.45, height 1.66
2512 [mm] "Chip Resistor, Body 6.3x3.2mm, IPC Medium Density"
  rect 1.3x3.4 smd: 1(-2.95,0) 2(2.95,0)
  silkscreen extent -1.9,-1.6 1.9,1.6, body extent -3.22,-1.67 3.22,1.67, height 0.71
7343-40 [mm] "Molded, 2-Leads, Body 7.3x4.3mm, Height 4mm"
  rect 2.4x2.9 smd: 1(-3.05,0) 2(3.05,0)
  silkscreen extent -3.8,-2.25 3.8,2.25, body extent -3.8,-2.25 3.8,2.25, height 4.01
CLF6045NI-D [mm] "SMD, 2-Leads, Body 6.3x6mm, Pitch 4.9mm"
  rect 2.1x2.2 smd: 1(-2.45,0) 2(2.45,0)
  silkscreen extent -3.25,-3.1 3.25,3.1, body extent -3.26,-3.11 3.26,3.11, height 4.8
CONN_PEC02SAAN [mm] "SULLINS"
  rect 1.5x1.5 hole 1.016: 1(-1.27,0)
  round 1.5 hole 1.016: 2(1.27,0)
  silkscreen extent -3.45,-1.27 2.54,1.27, body extent -2.54,-1.27 2.54,1.27, height 8.38
CONN_PEC03SAAN [mm] "SULLINS"
  rect 1.5x1.5 hole 1.016: 1(-2.54,0)
  round 1.5 hole 1.016: 2(0,0) 3(2.54,0)
  silkscreen extent -4.72,-1.27 3.81,1.27, body extent -3.84,-1.3 3.84,1.3, height 8.38
DBV0005A_N [mm] "SOT23, 5-Leads, Body 2.9x1.6mm, Pitch 0.95mm, Lead Span 2.8mm, IPC Medium Density"
  rect 1.1x0.65 smd: 1(-1.2,0.95) 2(-1.2,0) 3(-1.2,-0.95) 4(1.2,-0.95) 5(1.2,0.95)
  silkscreen extent -0.25,-1.55 0.25,1.55, body extent -1.42,-1.46 1.42,1.46, height 1.08
DBV0006A_N [mm] "SOT23, 6-Leads, Body 2.9x1.6mm, Pitch 0.95mm, Lead Span 2.8mm, IPC Medium Density"
  rect 1.1x0.65 smd: 1(-1.2,0.95) 2(-1.2,0) 3(-1.2,-0.95) 4(1.2,-0.95) 5(1.2,0) 6(1.2,0.95)
  silkscreen extent -1.68,-1.55 0.5,1.55, body extent -1.42,-1.46 1.42,1.46, height 1.11
DCK0006A_N [mm] "SOT23, 6-Leads, Body 2x1.3mm, Pitch 0.65mm, Lead Span 2.1mm, IPC Medium Density"
  rect 0.85x0.4 smd: 1(-0.95,0.65) 2(-0.95,0) 3(-0.95,-0.65) 4(0.95,-0.65) 5(0.95,0) 6(0.95,0.65)
  silkscreen extent -0.15,-1.1 0.15,1.1, body extent -1.14,-1 1.14,1, height 0.94
DCY0004A_N [mm] "SOT223/SC73, 4-Leads, Body 6.5x3.5mm, Pitch 2.3mm, Lead Span 7mm, IPC Medium Density"
  rect 2.4x1 smd: 1(-2.9,2.3) 2(-2.9,0) 3(-2.9,-2.3)
  rect 2.4x3.3 smd: 4(2.9,0)
  silkscreen extent -3.03,-3.35 1.4,3.47, body extent -3.5,-3.25 3.5,3.25, height 1.62
DDA0008E_N [mm]
  oval 2x0.6 smd: 1(-2.5,1.905) 2(-2.5,0.635) 3(-2.5,-0.635) 4(-2.5,-1.905) 5(2.5,-1.905) 6(2.5,-0.635) 7(2.5,0.635) 8(2.5,1.905)
  rect 2.4x3.1 smd: 9(0,0)
  silkscreen extent -3.22,-2.5 1.15,2.5, body extent -2.98,-2.45 2.98,2.45, height 1.5
DDC0005A_N [mil]
  rect 62x22 smd: 1(-46,37.4) 2(-46,0) 3(-46,-37.4) 4(46,-37.4) 5(46,37.4)
  silkscreen extent -34,-60 34,60, body extent -60,-60 60,60, height 43
DGQ0010D_NV_N [mm] "TSSOP, 10-Leads, Body 3x3mm, Pitch 0.5mm, Thermal Pad 1.88x1.57mm, IPC Medium Density"
  oval 1.7x0.3 smd: 1(-2.05,1) 2(-2.05,0.5) 3(-2.05,0) 4(-2.05,-0.5) 5(-2.05,-1) 6(2.05,-1) 7(2.05,-0.5) 8(2.05,0) 9(2.05,0.5) 10(2.05,1)
  rect 1.57x1.88 smd: 11(0,0)
  silkscreen extent -2.65,-1.55 0.9,1.55, body extent -2.45,-1.5 2.45,1.5, height 0.94
DRC0010A [mm] "SON, 10-Leads, Body 3x3mm, Pitch 0.5mm, Thermal Pad 2.4x1.65mm, TI Recommended"
  oval 0.6x0.24 smd: 1(-1.4,1) 2(-1.4,0.5) 3(-1.4,0) 4(-1.4,-0.5) 5(-1.4,-1) 6(1.4,-1) 7(1.4,-0.5) 8(1.4,0) 9(1.4,0.5) 10(1.4,1)
  rect 1.65x2.4 smd paste-0.825: 11(0,0)
  Top Layer region: 0.135,1.1 0.365,1.1 0.365,1.5 0.135,1.5
  Top Layer region: -0.135,1.5 -0.365,1.5 -0.365,1.1 -0.135,1.1
  Top Layer region: -0.135,-1.1 -0.365,-1.1 -0.365,-1.5 -0.135,-1.5
  Top Layer region: 0.135,-1.5 0.365,-1.5 0.365,-1.1 0.135,-1.1
  silkscreen extent -1.7,-1.7 1.7,1.7, body extent -1.55,-1.55 1.55,1.55, height 1.01
Keystone5000 [mil] "For Keystone 500x miniature loop terminals"
  round 80 hole 40: 1(0,0)
  silkscreen extent -58,-58 58,58, body extent -49,-49 49,49, height 182
Keystone5001 [mil] "For Keystone 500x miniature loop terminals"
  round 80 hole 40: 1(0,0)
  silkscreen extent -58,-58 58,58, body extent -49,-49 49,49, height 182
MOLEX_0676430910 [mm] "MOLEX"
  rrect50% 1.55x1.55 hole 0.95: 1(-3.5,2.7)
  round 1.55 hole 0.95: 2(-1,2.7) 3(1,2.7) 4(3.5,2.7)
  round 3.1 hole 2.3: 5(-6.57,-0.01) 6(6.57,-0.01)
  silkscreen extent -7.15,-10.31 7.25,5.6, body extent -8,-10.25 8,5.01, height 7.73
PWP0014E_N [mm] "TSOP, 14-Leads, Body 5x4.4mm, Pitch 0.65mm, Thermal Pad 3x3 mm, IPC Medium Density"
  oval 1.7x0.35 smd: 1(-2.85,1.95) 2(-2.85,1.3) 3(-2.85,0.65) 4(-2.85,0) 5(-2.85,-0.65) 6(-2.85,-1.3) 7(-2.85,-1.95) 8(2.85,-1.95) 9(2.85,-1.3) 10(2.85,-0.65) 11(2.85,0) 12(2.85,0.65) 13(2.85,1.3) 14(2.85,1.95)
  rect 2.46x2.31 smd: 15(0,0)
  silkscreen extent -3.5,-2.65 1.7,2.65, body extent -3.21,-2.5 3.21,2.5, height 0.99
SM_RADIAL_F [mm] "8 x 10.2mm:  Panasonic F"
  rect 4x2 smd: 1(-3.55,0) 2(3.55,0)
  silkscreen extent -4.25,-4.25 4.25,4.25, body extent -4.26,-4.26 4.26,4.26, height 10.5
SMB [mil] "Molded Diode, 2-Leads, Body 5.4x3.6mm, IPC Medium Density, based on OnSemi component dimensions"
  rect 85x107.99 smd: 1(-87.01,0) 2(87.01,0)
  silkscreen extent -155,-82 125,82, body extent -106,-71 106,71, height 91
SMC [mil] "Molded Diode, 2-Leads, Body 6.9x5.8mm, IPC Medium Density, based on OnSemi component dimensions and land patterns"
  rect 110x150 smd: 1(-140.49,0) 2(140.49,0)
  silkscreen extent -221,-124 189,124, body extent -156,-116 156,116, height 91
SO-8FL [mm] "ON SEMICONDUCTOR, DFN5 5x6, 1.27P, CASE 488AA"
  rect 1x0.75 smd: 1(-2.795,1.905) 2(-2.795,0.635) 3(-2.795,-0.635) 4(-2.795,-1.905)
  rect 4.055x4.56 smd: 5(0.698,0)
  Top Layer region: 3.2,-2.28 3.2,-1.53 2.65,-1.53 2.65,-2.28
  Top Layer region: 3.2,1.53 3.2,2.28 2.655,2.28 2.655,1.53
  Top Layer region: 0,-2.775 0,2.775 -0.905,2.775 -0.905,-2.775
  silkscreen extent -3.1,-2.6 3.1,2.9, body extent -3.17,-2.67 3.17,2.67, height 1.11
SOD-123 [mm] "On Semi recommended land pattern"
  rect 0.915x1.22 smd: 1(-1.637,0) 2(1.637,0)
  silkscreen extent -2.74,-1.17 2.03,1.17, body extent -1.93,-0.9 1.93,0.9, height 1.35
SOD-523 [mm] "NXP Semiconductor recommended land pattern, nominal STEP model"
  rect 0.8x0.6 smd paste-0.05: 1(-0.55,0) 2(0.55,0)
  silkscreen extent -1.6,-0.64 1.2,0.63, body extent -0.8,-0.4 0.8,0.4, height 0.72
SOT-23 [mm] "SOT23, 3-Leads, Body 2.9x1.3mm, Pitch 0.95mm, Lead Span 2.5mm, IPC Medium Density"
  rrect50% 1x0.6 smd: 1(-1.2,0.95) 2(-1.2,-0.95) 3(1.2,0)
  silkscreen extent -1.63,-1.5 0.7,1.5, body extent -1.16,-1.45 1.21,1.45, height 1
SOT-363 [mm]
  rect 0.6x0.42 smd mask+0.051: 1(-0.95,0.65) 2(-0.95,0) 3(-0.95,-0.65) 4(0.95,-0.65) 5(0.95,0) 6(0.95,0.65)
  silkscreen extent -0.38,-1.02 0.38,1.02, body extent -1.1,-1.1 1.1,1.1, height 1.12
TERM_BLK_ED555-2DS [mil]
  rect 100x100 hole 50: 1(0,0)
  round 100 hole 50: 2(138,0)
  silkscreen extent -93,-161 215,113, body extent -69,-150 207,106, height 323

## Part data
C1 C59: "CAP, CERM, 1000 pF, 100 V, +/- 5%, C0G/NP0, 0603"
C2: "CAP, CERM, 0.01 µF, 100 V, +/- 10%, X7R, 0603"
C3: "CAP, CERM, 0.22 µF, 50 V, +/- 10%, X7R, 0603"
C4: "CAP, AL, 100 µF, 50 V, +/- 20%, 0.34 ohm, SMD"
C5 C9 C22 C32: library part C3225X7R1E106M, "CAP, CERM, 4.7uF, 50V, +/-20%, X7R, 1210"
C6 C13 C51 C52 C54 C55: library part C1608X7R1C105K, "CAP, CERM, 1uF, 25V, +/-10%, X7R, 0603"
C7 C10 C11 C23 C24 C33 C34 C42 C48 C50 C58: "CAP, CERM, 0.1uF, 50V, +/-10%, X7R, 0603"
C8: "CAP, CERM, 0.01 µF, 50 V, +/- 10%, X7R, 0603"
C12 C49: "CAP, CERM, 10uF, 10V, +/-10%, X7R, 0805"
C14 C16 C29 C44: library part C3225X7R1C226M, "CAP, CERM, 22 µF, 16 V, +/- 20%, X7R, 1210"
C15 C20 C27 C39 C40 C57: library part C1608C0G1H102J, "CAP, CERM, open, 0603"
C17 C30: library part C3225X7R1C226M, "CAP, open, 1210"
C18: "CAP, CERM, 0.047 µF, 50 V, +/- 10%, X7R, 0603"
C19 C31 C35: "CAP, CERM, 150 pF, 50 V, +/- 5%, C0G/NP0, 0603"
C21: "CAP, CERM, 6800 pF, 25 V, +/- 5%, C0G/NP0, 0603"
C25 C28 C36 C45: "CAP, CERM, 0.1uF, 50V, +/-10%, X7R, 0402"
C26 C41 C46: "CAP, CERM, 10 pF, 50 V, +/- 5%, C0G/NP0, 0603"
C37: "CAP, CERM, 0.022 µF, 50 V, +/- 10%, X7R, 0603"
C38: "CAP, CERM, 1500 pF, 50 V, +/- 5%, C0G/NP0, 0603"
C43: library part 10TPB220M, "CAP, open, 7343-40 SMD"
C47 C53 C56: "CAP, CERM, 10 µF, 10 V, +/- 10%, X7R, 0805"
D1 D2: "Diode, Schottky, 45 V, 10 A, 6.15x1.00x5.15mm"
D3: library part 1.5SMC6.8A, "Diode, TVS, Uni, 33 V, 1500 W, SMC"
D4: library part 1PS79SB70,115, "Diode, Schottky, 30 V, 0.2 A, SOD-523"
D5: "Diode, Zener, 3.3 V, 500 mW, SOD-123"
D6: "Diode, Zener, 18 V, 500 mW, SOD-123"
D7: library part B130LAW-7-F, "Diode, Schottky, 30V, 1.5A, SOD-123"
D8: "Diode, Zener, 12 V, 500 mW, SOD-123"
D9 D13: library part MBRS260T3G, "Diode, Schottky, 60V, 3A, SMB"
D10 D11 D14 D16 D18 D21 D22 D23: "Diode, Ultrafast, 75V, 0.3A, SOT-23"
D12 D15 D20: "Diode, Zener, 2.4V, 500 mW, SOD-123"
D17 D19: "Diode, Schottky, 60V, 2A, SMB"
J1 J3 J7 J9 J23 J24 J26 J31 J33: "Terminal Block, 6A, 3.5mm Pitch, 2-Pos, TH"
J2 J4 J5 J6 J8 J11 J12 J13 J16 J17 J18 J19 J22 J25 J28 J29 J30 J35 J36: "Header, 100mil, 2x1, Tin, TH"
J10 J27 J32 J34: "Header, 100mil, 3x1, Tin, TH"
J14 J15 J20 J21: "Connector, Receptacle, USB Standard, R/A, Top Mount TH"
L1: "Ferrite Bead, 115 ohm @ 100MHz, 10A, SMD, 2-Leads, Body 8.74x4.65mm"
L2 L4: "Inductor, Wirewound, Ferrite, 2.2 µH, 4.1 A, 0.015 ohm, SMD"
L3 L5: "Inductor, Wirewound, Ferrite, 4.7 µH, 3.1 A, 0.023 ohm, SMD"
Q1: library part "BCR 48PN E6327, Infineon Technologies", "Transistor, NPN/PNP Pair, 50 V, 0.1 A, SOT-363"
Q2: library part "BC 846PN H6327, Infineon Technologies", "Transistor, NPN/PNP Pair, 45 V, 0.1 A, SOT-363"
R1: "RES, 7.5, 5%, 0.75 W, 2010"
R2: "RES, 20.0 k, 1%, 0.1 W, 0603"
R3 R4 R13 R14 R19 R31 R34 R36 R44 R49 R50 R53: "RES, 10.0 k, 1%, 0.1 W, 0603"
R5: "RES, 10.0 k, 1%, 0.125 W, 0805"
R6: "RES, 2.00 k, 1%, 0.25 W, 1206"
R7: "RES, 2.87 k, 1%, 0.1 W, 0603"
R8: "RES, 3.01 k, 1%, 0.1 W, 0603"
R9 R43: "RES, 100 k, 1%, 0.1 W, 0603"
R10: "RES, 34.0 k, 1%, 0.1 W, 0603"
R11: "RES, 110, 1%, 0.1 W, 0603"
R12 R29 R45: library part CRCW20102R70JNEF, "RES, open, 2010"
R15 R26: library part CRCW060312K1FKEA, "RES, 12.1 k, 0.1%, 0.1 W, 0603"
R16: "RES, 53.6 k, 1%, 0.1 W, 0603"
R17 R18: "RES, 15.0, 1%, 0.25 W, 1206"
R20 R28 R38: "RES, 0, 5%, 0.1 W, 0603"
R21 R30 R47: "RES, 200, 1%, 0.1 W, 0603"
R22 R35: "RES, 0.2, 1%, 2 W, 2512"
R23 R37: "RES, 0.01, 1%, 0.5 W, 1206"
R24 R39: "RES, 4.02 k, 1%, 0.1 W, 0603"
R25 R32 R41 R46 R52: "RES, 4.99 k, 1%, 0.1 W, 0603"
R27 R40: "RES, 63.4 k, 1%, 0.1 W, 0603"
R33 R48: "RES, 124 k, 1%, 0.1 W, 0603"
R42: "RES, 54.9 k, 1%, 0.1 W, 0603"
R51: "RES, 2.49 k, 1%, 0.1 W, 0603"
R54: "RES, 49.9 k, 1%, 0.1 W, 0603"
TP1 TP2 TP4 TP6 TP7 TP8 TP9 TP10 TP11 TP12 TP13 TP17 TP19 TP20 TP23 TP25 TP26 TP27 TP30 TP32 TP34 TP36 TP37 TP40 TP41 TP42: "Test Point, Miniature, Red, TH"
TP3 TP5 TP14 TP15 TP16 TP18 TP21 TP22 TP24 TP28 TP29 TP31 TP33 TP35 TP38 TP39: "Test Point, Miniature, Black, TH"
U1: "Low Dropout Voltage Tracking LDO, DBV0005A"
U2 U4: library part LMR14030PDDAR, "LMR14030PQDDAQ1, DDA0008E"
U3: "3-A High Voltage Boost Converter with Soft-start and Programmable Switching Frequency, PWP0014E"
U5 U7: library part INA213AIDCK, "Voltage Output, High or Low Side Measurement, Bi-Directional Zero-Drift Series Current-Shunt Monitor, DCK0006A"
U6: "1.5-A 42-V STEP-DOWN SWIFT DC-DC CONVERTER WITH Eco-mode CONTROL, DGQ0010D"
U8 U9: "High Voltage Ultra Low Iq - Low Drop Out Regulator, DCY0004A"
U10: "Single Output Automotive LDO, 200 mA, Fixed 3.3 V Output, 2 to 5.5 V Input, with Low IQ, 5-pin SOT (DDC), -40 to 125 degC, Green (RoHS & no Sb/Br)"
U11: "Single Output Automotive LDO, 300 mA, Fixed 1.8 V Output, 2 to 5.5 V Input, with Low IQ, 5-pin SOT (DDC), -40 to 125 degC, Green (RoHS & no Sb/Br)"
U12: "Single Output Automotive LDO, 500 mA, Adjustable 0.8 to 3.6 V Output, 0.8 to 5.5 V Input, with Programmable Soft Start, 10-pin SON (DRC), -40 to 125 degC, Green (RoHS & no Sb/Br)"
U13: library part TPS3808G18QDBVRQ1, "LOW-QUIESCENT-CURRENT PROGRAMMABLE-DELAY SUPERVISORY CIRCUIT, DBV0006A"

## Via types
v1: diameter 34, hole 16, Top Layer to Bottom Layer, 193 vias
v2: diameter 19.68, hole 7.87, Top Layer to Bottom Layer, tented top, 12 vias
v3: diameter 18, hole 8, Top Layer to Bottom Layer, 5 vias
v4: diameter 15.75, hole 7.87, Top Layer to Bottom Layer, 4 vias
v5: diameter 19.68, hole 7.87, Top Layer to Bottom Layer, 4 vias

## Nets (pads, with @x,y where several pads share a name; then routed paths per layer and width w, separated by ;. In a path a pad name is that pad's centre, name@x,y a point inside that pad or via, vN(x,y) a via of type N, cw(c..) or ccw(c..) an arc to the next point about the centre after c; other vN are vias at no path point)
"3.3V PG": J8.1 J35.2 R13.2 U2.6 | length 3194.8
  Top Layer w20: J8.1@985,655 992.8,662.8 R13.2@992.8,840 995,842.2 U2.6@995,921.57
  Bottom Layer w15: 1238.15,1180 1240.78,1180 1276.16,1215.37 1322.94,1215.37 1358.31,1180 1361.85,1180
  Bottom Layer w20: J8.1@985,655 985,803.5 870,918.5 870,1075 975,1180 1238.15,1180 ; 1361.85,1180 1570,1180 1582.4,1192.4 1582.4,1422.4 2405,2245 2507.96,2245 2510.37,2247.4 2602.4,2247.4 J35.2@2655,2300
3.3V_SW: C16.1 C17.1 C58.1 J6.1 J9.1 J28.2 J29.2 L2.2 R4.2 R10.2 R13.1 R34.1 R36.1 R54.2 TP13.1 U13.6 | length 6977.1
  Top Layer w20: R10.2@870,793.5 878.5,785 v1(925,785) ; R13.1@929.8,840 925,835.2 v1(925,785) ; J9.1@1421.1,295 1326.1,200 990,200 935,255 935,745 925,755 v1(925,785) ; R34.1@2718.5,645 2720,643.5 v1(2720,595) ; R36.1@3144.68,1728.5 3144.68,1675.32 v1(3145,1675)
  Top Layer w25: R4.2@200,2771.5 201.5,2770 v1(250,2770) ; U13.6@2279.06,2578.07 2279.06,2544.96 2294.8,2529.21 C58.1@2294.8,2515.47 R54.2@2294.8,2445.47 2294.8,2387.07 2316.2,2365.67 2316.2,2228.8 2345,2200 J29.2@2530,2200
  Top Layer w50: J9.1@1421.1,295 1526.1,190 TP13.1@1756.1,190
  Bottom Layer w15: J29.2@2530,2200 2595,2200 2917.63,1877.37 3158.09,1877.37 3180,1855.47 3180,1805 3145,1770 v1(3145,1675)
  Bottom Layer w20: v1(250,2770) 121,2641 121,2234 169.13,2185.87 390.87,2185.87 422.87,2217.87 533.97,2217.87 556.85,2195 1360,2195 1425,2130 1620,2130 1685,2195 J28.2@1705,2195 ; TP13.1@1756.1,190 1860,190 1945,105 2340,105 2455,220 2455,525 2545.68,615.68 2699.32,615.68 v1(2720,595)
5V#1PG: J16.1 R34.2 U4.6 | length 248.1
  Top Layer w20: J16.1@2745,510 2781.5,546.5 R34.2@2781.5,645 2785,648.5 U4.6@2785,741.57
GND: C1.2 C2.2 C3.2 C4.2 C5.1 C6.2 C7.2 C8.2 C9.1 C10.2 C12.2 C13.2 C14.2 C16.2 C17.2 C18.2 C20.2 C21.2 C22.1 C23.2 C25.2 C28.2 C29.2 C30.2 C32.1 C33.2 C36.2 C37.2 C40.2 C42.2 C43.2 C44.2 C45.2 C46.2 C47.2 C48.2 C49.2 C50.2 C51.2 C52.2 C53.2 C54.2 C55.2 C56.2 C57.2 C58.2 C59.2 D3.2 D5.2 D6.2 D9.2 D11.1 D12.2 D13.2 D15.2 D16.1 D19.2 D20.2 D21.1 J1.2 J3.2 J5.2 J8.2 J9.2 J10.3 J12.2 J13.2 J14.4 J14.5 J14.6 J15.4 J15.5 J15.6 J16.2 J18.2 J19.2 J20.4 J20.5 J20.6 J21.4 J21.5 J21.6 J23.2 J24.2 J26.2 J27.3 J30.2 J31.2 J32.3 J33.2 J34.3 J36.2 Q1.1 Q2.1 R7.2 R8.1 R9.2 R12.1 R14.1 R15.1 R16.1 R17.1 R18.1 R21.1 R29.1 R30.1 R31.1 R32.2 R43.1 R44.1 R45.1 R46.2 R47.1 R52.1 TP3.1 TP5.1 TP15.1 TP16.1 TP18.1 TP21.1 TP22.1 TP24.1 TP28.1 TP29.1 TP31.1 TP33.1 TP35.1 TP38.1 TP39.1 U1.2 U1.5 U2.7 U2.9 U3.7 U3.11 U3.12 U3.13 U3.14 U3.15 U4.7 U4.9 U5.2 U6.9 U6.11 U7.2 U8.2 U8.4 U9.2 U9.4 U10.2 U11.2 U12.6 U12.11 U13.2 | length 1048.5
  Top Layer w10: U12.11@1996.3,2515 2030,2481.3 2030,2475 2030.63,2475.63 U12.6@2051.42,2475.63 ; v3(3114.68,1930) 3134.37,1949.69 U6.9@3195.39,1949.69 3249.37,1949.69 v1(3259.68,1960)
  Top Layer w14: v1(1930,1025) 1937.72,1032.72 U3.7@1937.72,1094.11 ; U4.9@2810,840 2810,815 2835,790 U4.7@2835,741.57
  Top Layer w15: v1(295,2075) 343.31,2075 Q1.1@352.95,2065.36 ; U5.2@3354.01,197.6 3354.01,156.38 C25.2@3365.39,145
  Top Layer w20: D6.2@304.47,1895 304.47,1899.47 v1(345,1940) ; v1(1036.3,785) 1045,793.7 U2.7@1045,921.57 ; v1(2825,600) 2835,610 U4.7@2835,741.57 ; v1(3259.68,1960) 3420,1960 v1(3425,1955)
  other v1: 3320,150 3455,170 3285,185 2975,270 2790,285 1185,330 2760,435 2105,445 525,450 1300,475 1075,480 2105,495 525,500 2105,545 525,550 2105,595 3250,625 3300,625 3350,625 3395,625 3440,625 3265,710 3265,760 1810,765 2080,770 2610,795 1470,800 1520,800 1565,800 1615,800 1660,800 2055,810 2105,810 3103.58,815 3155,815 2715,820 2525,850 2610,850 3103.58,860 2715,865 1490,880 3105,905 1490,935 1930,980 1118,990 1318.9,990 1370,990 920,995 1760,995 1320,1035 1370,1035 2960,1040 3010,1040 920,1045 1118,1045 1740,1060 3035,1090 660,1105 705,1105 3035,1135 705,1155 1741.48,1168.93 745,1180 3035,1185 705,1205 785,1210 1190,1220 1255,1240 785,1260 1255,1290 2505,1295 2190,1300 2055,1330 1255,1335 2095,1350 2145,1350 2190,1350 2005,1355 1255,1385 180,1445 305,1445 239.95,1446 180,1590 305,1590 239.95,1594 2760,1625 3045,1625 3199.68,1675 3364.68,1675 2840,1755 2775,1765 3093.23,1845 3580,1950 3015,2025 3015,2071.42 2780,2090 2815,2150 2865,2150 2915,2150 3565,2170 2915,2200 330,2239.68 3020,2252.01 175,2265 690,2270 1040,2270 3020,2305 175,2315 590,2350 645,2350 940,2350 990,2350 2190,2360 3020,2360 1980,2365 175,2370 490,2375 3215,2400 1540,2415 175,2420 1275,2420 770,2450 1115,2450 1440,2450 2535,2450 2770,2450 3215,2450 2240,2460 490,2470 540,2470 3070,2485 3125,2485 2670,2495 3215,2500 2406.3,2515.47 585,2545 640,2545 935,2545 990,2545 3185,2545 1085,2570 730.98,2577.95 3185,2605 2426.3,2615.47 190,2650 735,2695 1085,2695 2030,2695 2090,2695 2135,2695 2060,2735 3485,2815 3435,2865 3500,2970 3455,2995 3510,3040 3435,3130
  other v2: 2758.82,814.41 2810,814.41 2861.18,814.41 2758.82,865.59 2810,865.59 2861.18,865.59 968.82,994.41 1020,994.41 1071.18,994.41 968.82,1045.59 1020,1045.59 1071.18,1045.59
  other v3: 3095.68,1905 3134.68,1905 3094.68,1956 3134.68,1956
  other v4: 1984.96,952.38 2044.02,952.38 1984.96,1011.44 2044.02,1011.44
  other v5: 1996.3,2477.6 1973.66,2515 2018.94,2515 1996.3,2552.4
NetC1_1: C1.1 C2.1 J1.1 L1.1 TP1.1
NetC5_2: C5.2 J2.1 Q2.4 R1.1 R3.2 U1.4 | length 615.1
  Top Layer w15: Q2.4@267.4,2564.41 340.59,2564.41 360,2545 R1.1@360,2499.13
  Top Layer w20: U1.4@367.4,2286.93 367.4,2277.6 416.5,2228.5 R3.2@430,2228.5
  Top Layer w25: U1.4@360,2294.33 U1.4@367.4,2286.93
  Top Layer w40: U1.4@360,2294.33 C5.2@360,2377.09
  Top Layer w45: C5.2@360,2377.09 R1.1@360,2499.13 449.13,2499.13 J2.1@500,2550
NetC7_1: C7.1 Q2.6 R4.1 TP6.1 | length 321.3
  Top Layer w15: TP6.1@150,2870 140,2860 C7.1@140,2751.5 161.5,2730 178.5,2730 R4.1@200,2708.5 200,2705 267.4,2637.6 Q2.6@267.4,2615.59
NetC8_1: C8.1 D6.1 R6.2 R9.1 U1.1 | length 391.2
  Top Layer w25: D6.1@175.53,1895 175.53,2097.03 R9.1@198.5,2120 200,2121.5 200,2168.5 C8.1@230,2198.5 286.54,2198.5 U1.1@292.6,2192.44
NetC9_2: C9.2 C10.1 J4.2 U2.2
NetC11_1: C11.1 U2.1 | length 105.5
  Top Layer w22: U2.1@1095,1118.43 1105,1128.43 1105,1150 1116.5,1161.5 C11.1@1170,1161.5
NetC12_1: C12.1 C13.1 J6.2 J10.1 L3.1 TP10.1 U3.3
NetC14_1: C14.1 D7.1 D8.1 J7.2 TP12.1 | length 294.7
  Top Layer w25: D8.1@1995,662.95 v1(1995,710)
  Bottom Layer w25: v1(1995,710) 2080,710 v1(2195,595)
NetC15_2: C15.2 R12.2 | length 114.5
  Top Layer w40: R12.2@1369.45,905 1369.45,882.56 1416.5,835.51 C15.2@1416.5,810
NetC18_1: C18.1 U3.5 | length 156.3
  Top Layer w10: U3.5@1988.9,1094.11 1988.9,1165.25 1984.61,1169.54 1984.61,1220.54 C18.1@2004.49,1240.41
NetC19_1: C19.1 D10.1 D11.3 R21.2 U3.6 | length 355.7
  Top Layer w10: C19.1@1914.49,1195.41 1963.31,1146.59 U3.6@1963.31,1094.11
  Top Layer w15: R21.2@1855.98,1196.91 1855.98,1127.66 D11.3@1886.73,1096.91 ; D10.1@1856.73,1259.51 1857.48,1258.76 1857.48,1195.41 C19.1@1914.49,1195.41
NetC19_2: C19.2 R20.2 | length 57
  Top Layer w20: C19.2@1914.49,1258.41 R20.2@1914.49,1315.41
NetC20_1: C20.1 R19.2 U3.8 | length 122.6
  Top Layer w14: 1915.3,869.7 U3.8@1937.72,869.7
  Top Layer w20: R19.2@1870.98,871.91 1873.19,869.7 1915.3,869.7
  Top Layer w25: C20.1@1870.98,816.91 R19.2@1870.98,871.91
NetC21_1: C21.1 R19.1 | length 59.1
  Top Layer w25: R19.1@1807.99,871.91 1807.99,928.92 C21.1@1809.49,930.41
NetC22_2: C22.2 C23.1 J11.2 U4.2
NetC24_1: C24.1 U4.1 | length 118.3
  Top Layer w20: U4.1@2885,938.43 2898.43,938.43 2898.43,961.57 2890,970 2943.5,970 C24.1@2955,981.5
NetC24_2: C24.2 C27.1 D13.1 L4.1 TP19.1 U4.8 | length 350.8
  Top Layer w20: C24.2@2955,918.5 2958.5,915 v1(3005,915)
  Bottom Layer w20: v1(2910,655) 2935,680 2935,845 v1(3005,915)
NetC25_1: C25.1 C29.1 C30.1 J15.1 L4.2 R23.1 R25.1 R27.2 TP20.1 U5.3 U5.5 | length 1204.3
  Top Layer w15: R23.1@3307.91,350 3307.91,342.09 3354.01,295.99 U5.5@3354.01,272.4 3354.01,245.19 3379.6,219.6 U5.3@3379.6,197.6 3379.6,185.4 3412.63,152.37 C25.1@3412.63,145
  Top Layer w20: v1(2660,575) R27.2@2660,622.95
  Bottom Layer w20: v1(2660,575) 2675,560 3385,560 v1(3510,435)
  other v1: 3175,330
NetC26_1: C26.1 R24.2 | length 65
  Top Layer w20: C26.1@2660,1156.5 R24.2@2725,1156.5
NetC26_2: C26.2 C31.1 D14.1 D16.3 R26.1 R30.2 | length 416.5
  Top Layer w20: D14.1@2467.6,1052.76 2467.6,1049.29 2519.65,997.24 D16.3@2560,997.24 2597.76,1035 R26.1@2663.5,1035 ; C31.1@2605,1093.5 C26.2@2660,1093.5 2663.5,1090 R26.1@2663.5,1035 ; R30.2@2660,971.5 2663.5,975 R26.1@2663.5,1035
NetC27_2: C27.2 R29.2 | length 116.6
  Top Layer w30: R29.2@3144.45,730 3196.5,677.95 C27.2@3196.5,635
NetC28_1: C28.1 J14.1 R22.1 R23.2 TP41.1 U5.4 | length 154.2
  Top Layer w15: R23.2@3422.09,350 3422.09,341.06 3379.6,298.57 U5.4@3379.6,272.4 3388.38,263.62 C28.1@3435,263.62
NetC31_2: C31.2 R28.2 | length 62
  Top Layer w20: C31.2@2605,1156.5 R28.2@2605,1218.5
NetC32_2: C32.2 C33.1 J17.2 U6.2 | length 82.1
  Top Layer w11: 3000.31,1949.69 U6.2@3033.98,1949.69
  Top Layer w12: C33.1@2959.68,1968.5 2978.19,1950 3000,1950 3000.31,1949.69
NetC34_1: C34.1 U6.1 | length 86.5
  Top Layer w10: U6.1@3033.98,1969.37 U6.1@3033.98,1973.41
  Top Layer w15: U6.1@3033.43,1973.96 U6.1@3033.98,1973.41
  Top Layer w20: U6.1@3033.43,1973.96 3035,1975.53 3035,1980 3083.19,2028.19 C34.1@3083.19,2035
NetC34_2: C34.2 C39.1 D19.1 L5.1 TP26.1 U6.10 | length 100
  Top Layer w10: U6.10@3195.39,1969.37 U6.10@3197.86,1971.84
  Top Layer w15: U6.10@3185.91,1973.96 3197.86,1973.96 U6.10@3197.86,1971.84
  Top Layer w20: C34.2@3146.18,2035 3190,1991.18 3190,1981.82 U6.10@3197.86,1973.96
NetC35_1: C35.1 C41.2 D18.1 D21.3 R42.1 R47.2 | length 314.2
  Top Layer w20: D18.1@2987.09,1647.24 2987.09,1689.09 C35.1@2971.18,1705 2971.18,1762.01 C41.2@2969.68,1763.5 R42.1@3029.68,1763.5 3054.84,1738.35 3074.84,1738.35 R47.2@3084.68,1728.5 D21.3@3084.68,1667.24
NetC35_2: C35.2 R38.2 | length 62
  Top Layer w20: R38.2@2846.18,1705 C35.2@2908.19,1705
NetC36_1: C36.1 C42.1 D17.1 J21.1 R37.1 R40.2 R41.1 TP27.1 U7.3 U7.5 | length 768.2
  Top Layer w15: R37.1@3265.31,2992.91 3312.4,3040 U7.5@3337.91,3040 3365,3040 3390.59,3065.59 U7.3@3412.72,3065.59 3435.75,3088.62 C36.1@3465.31,3088.62
  Top Layer w20: R40.2@3254.68,1728.5 3259.68,1723.5 v1(3259.68,1675) 3259.68,1660.32 3285,1635 3420,1635 3595,1810 TP27.1@3595,1850
NetC37_1: C37.1 U6.4 | length 218.9
  Top Layer w10: C37.1@2833.23,1866.5 2861.73,1895 2955,1895 2970.32,1910.32 U6.4@3033.98,1910.32
NetC38_1: C38.1 C46.1 U6.8 | length 242.6
  Top Layer w10: U6.8@3195.39,1930 3245,1930 3275,1900 3275,1885 3306.5,1853.5 C46.1@3309.68,1853.5 3369.68,1913.5 C38.1@3369.68,1916.5
NetC38_2: C38.2 R43.2 | length 62
  Top Layer w20: R43.2@3369.68,1791.5 C38.2@3369.68,1853.5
